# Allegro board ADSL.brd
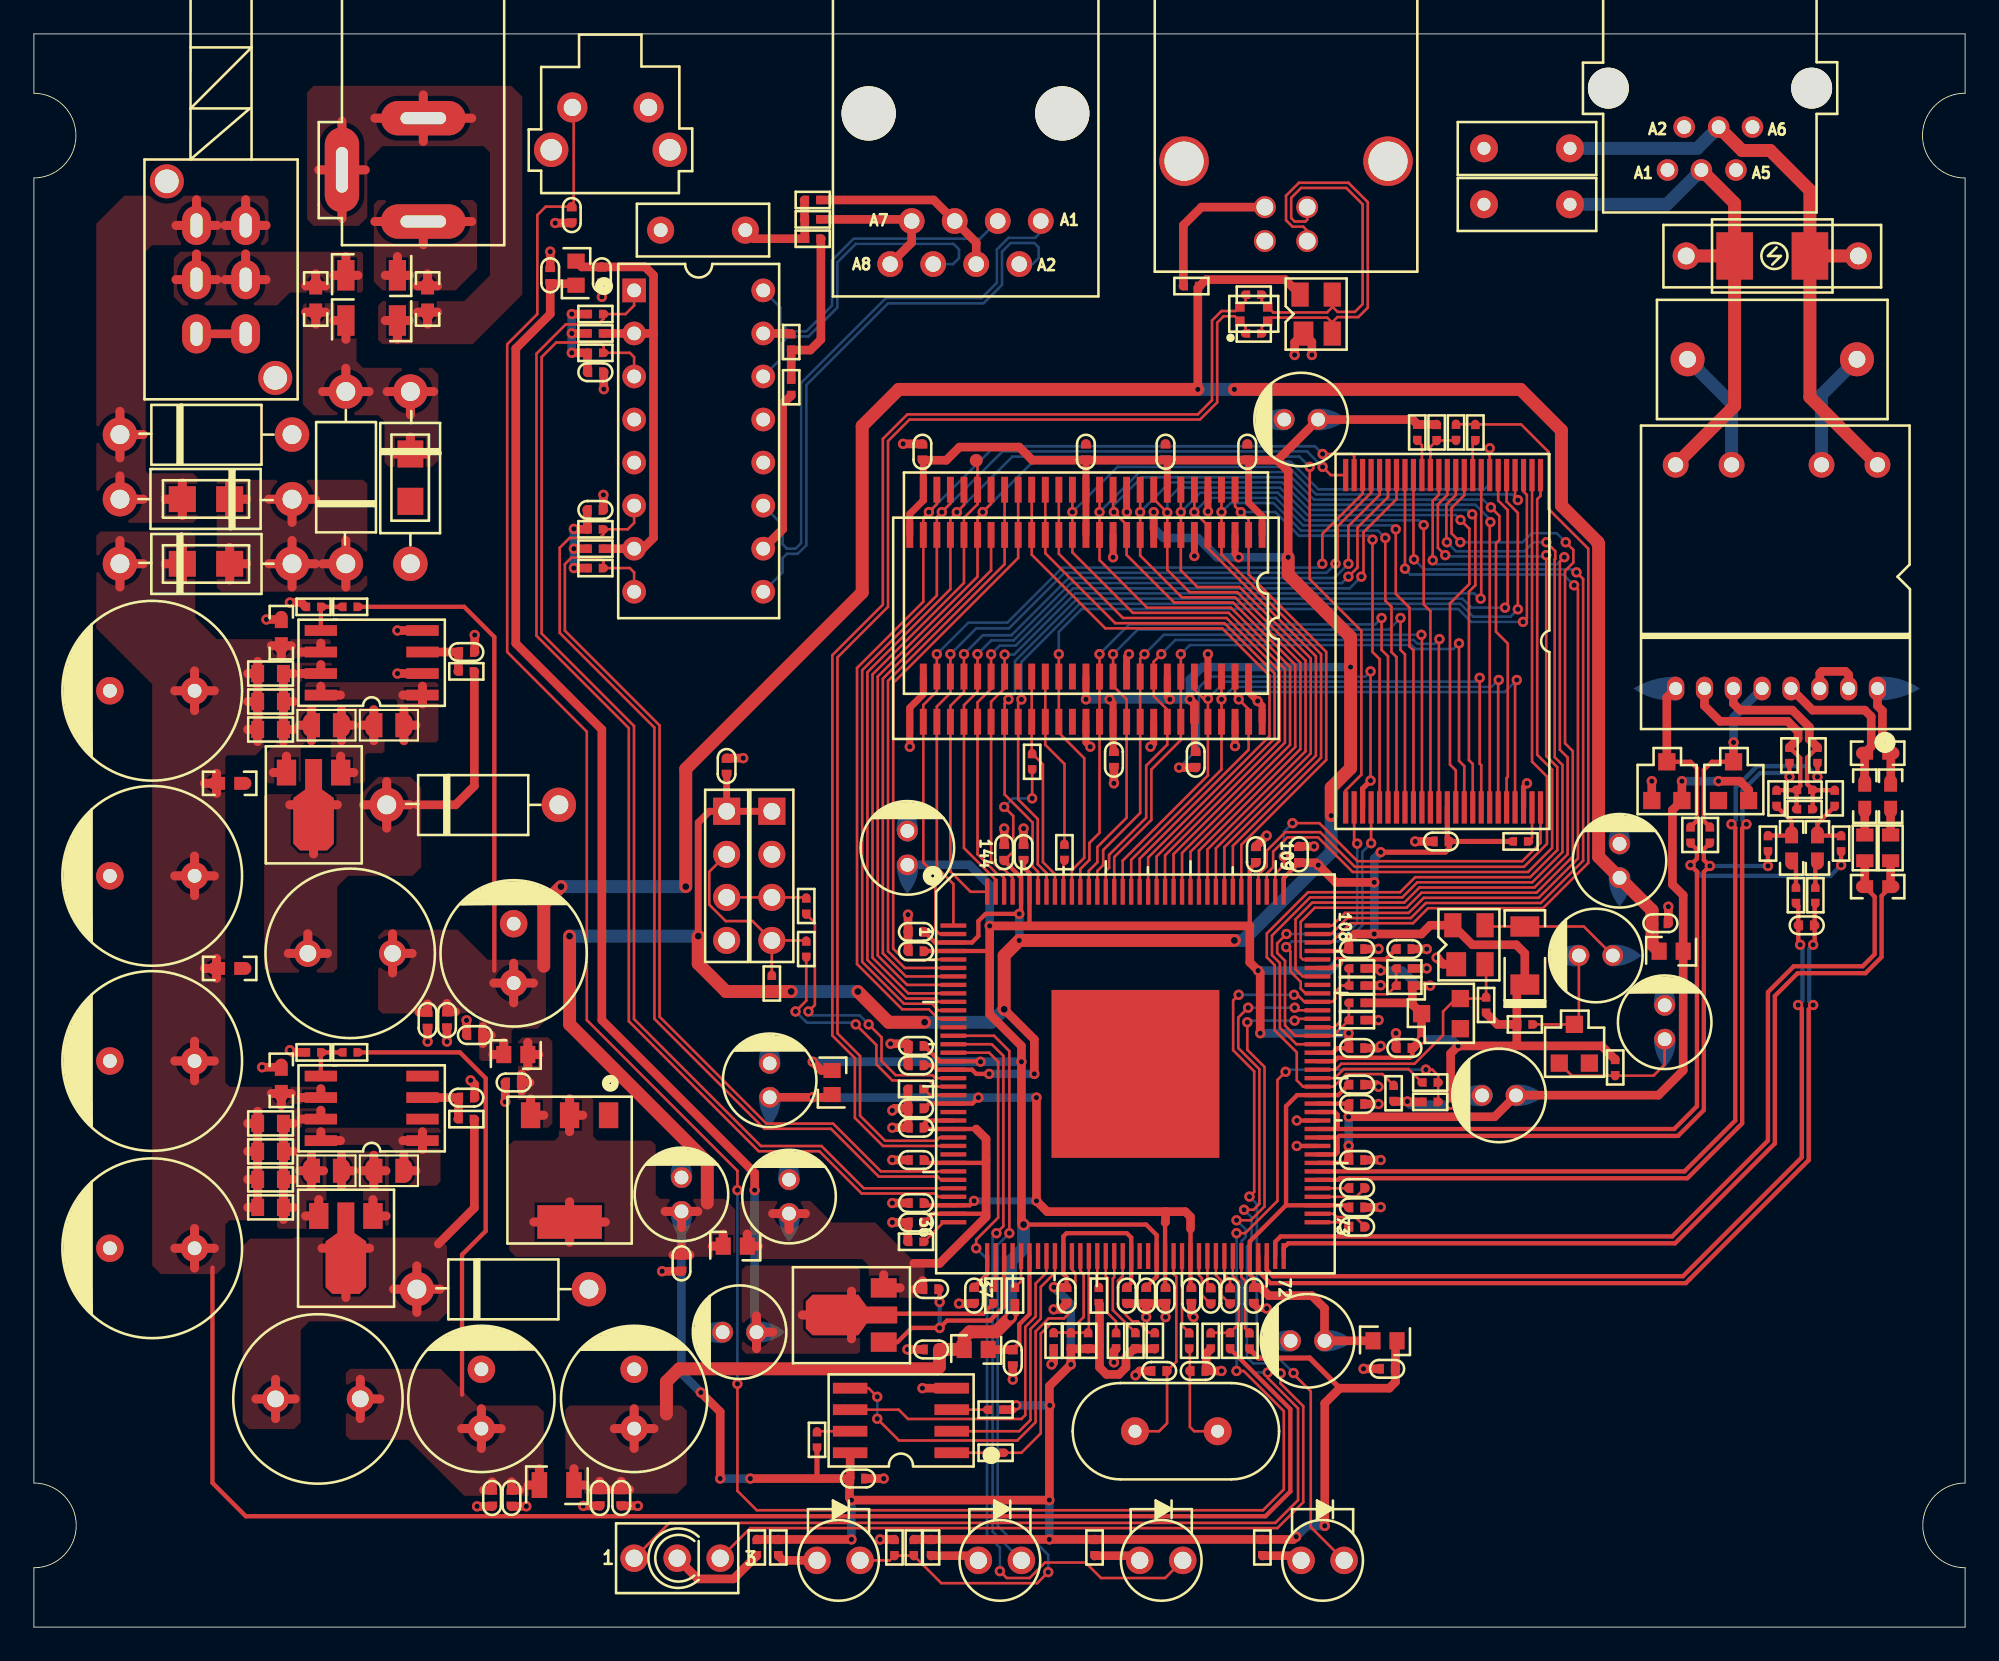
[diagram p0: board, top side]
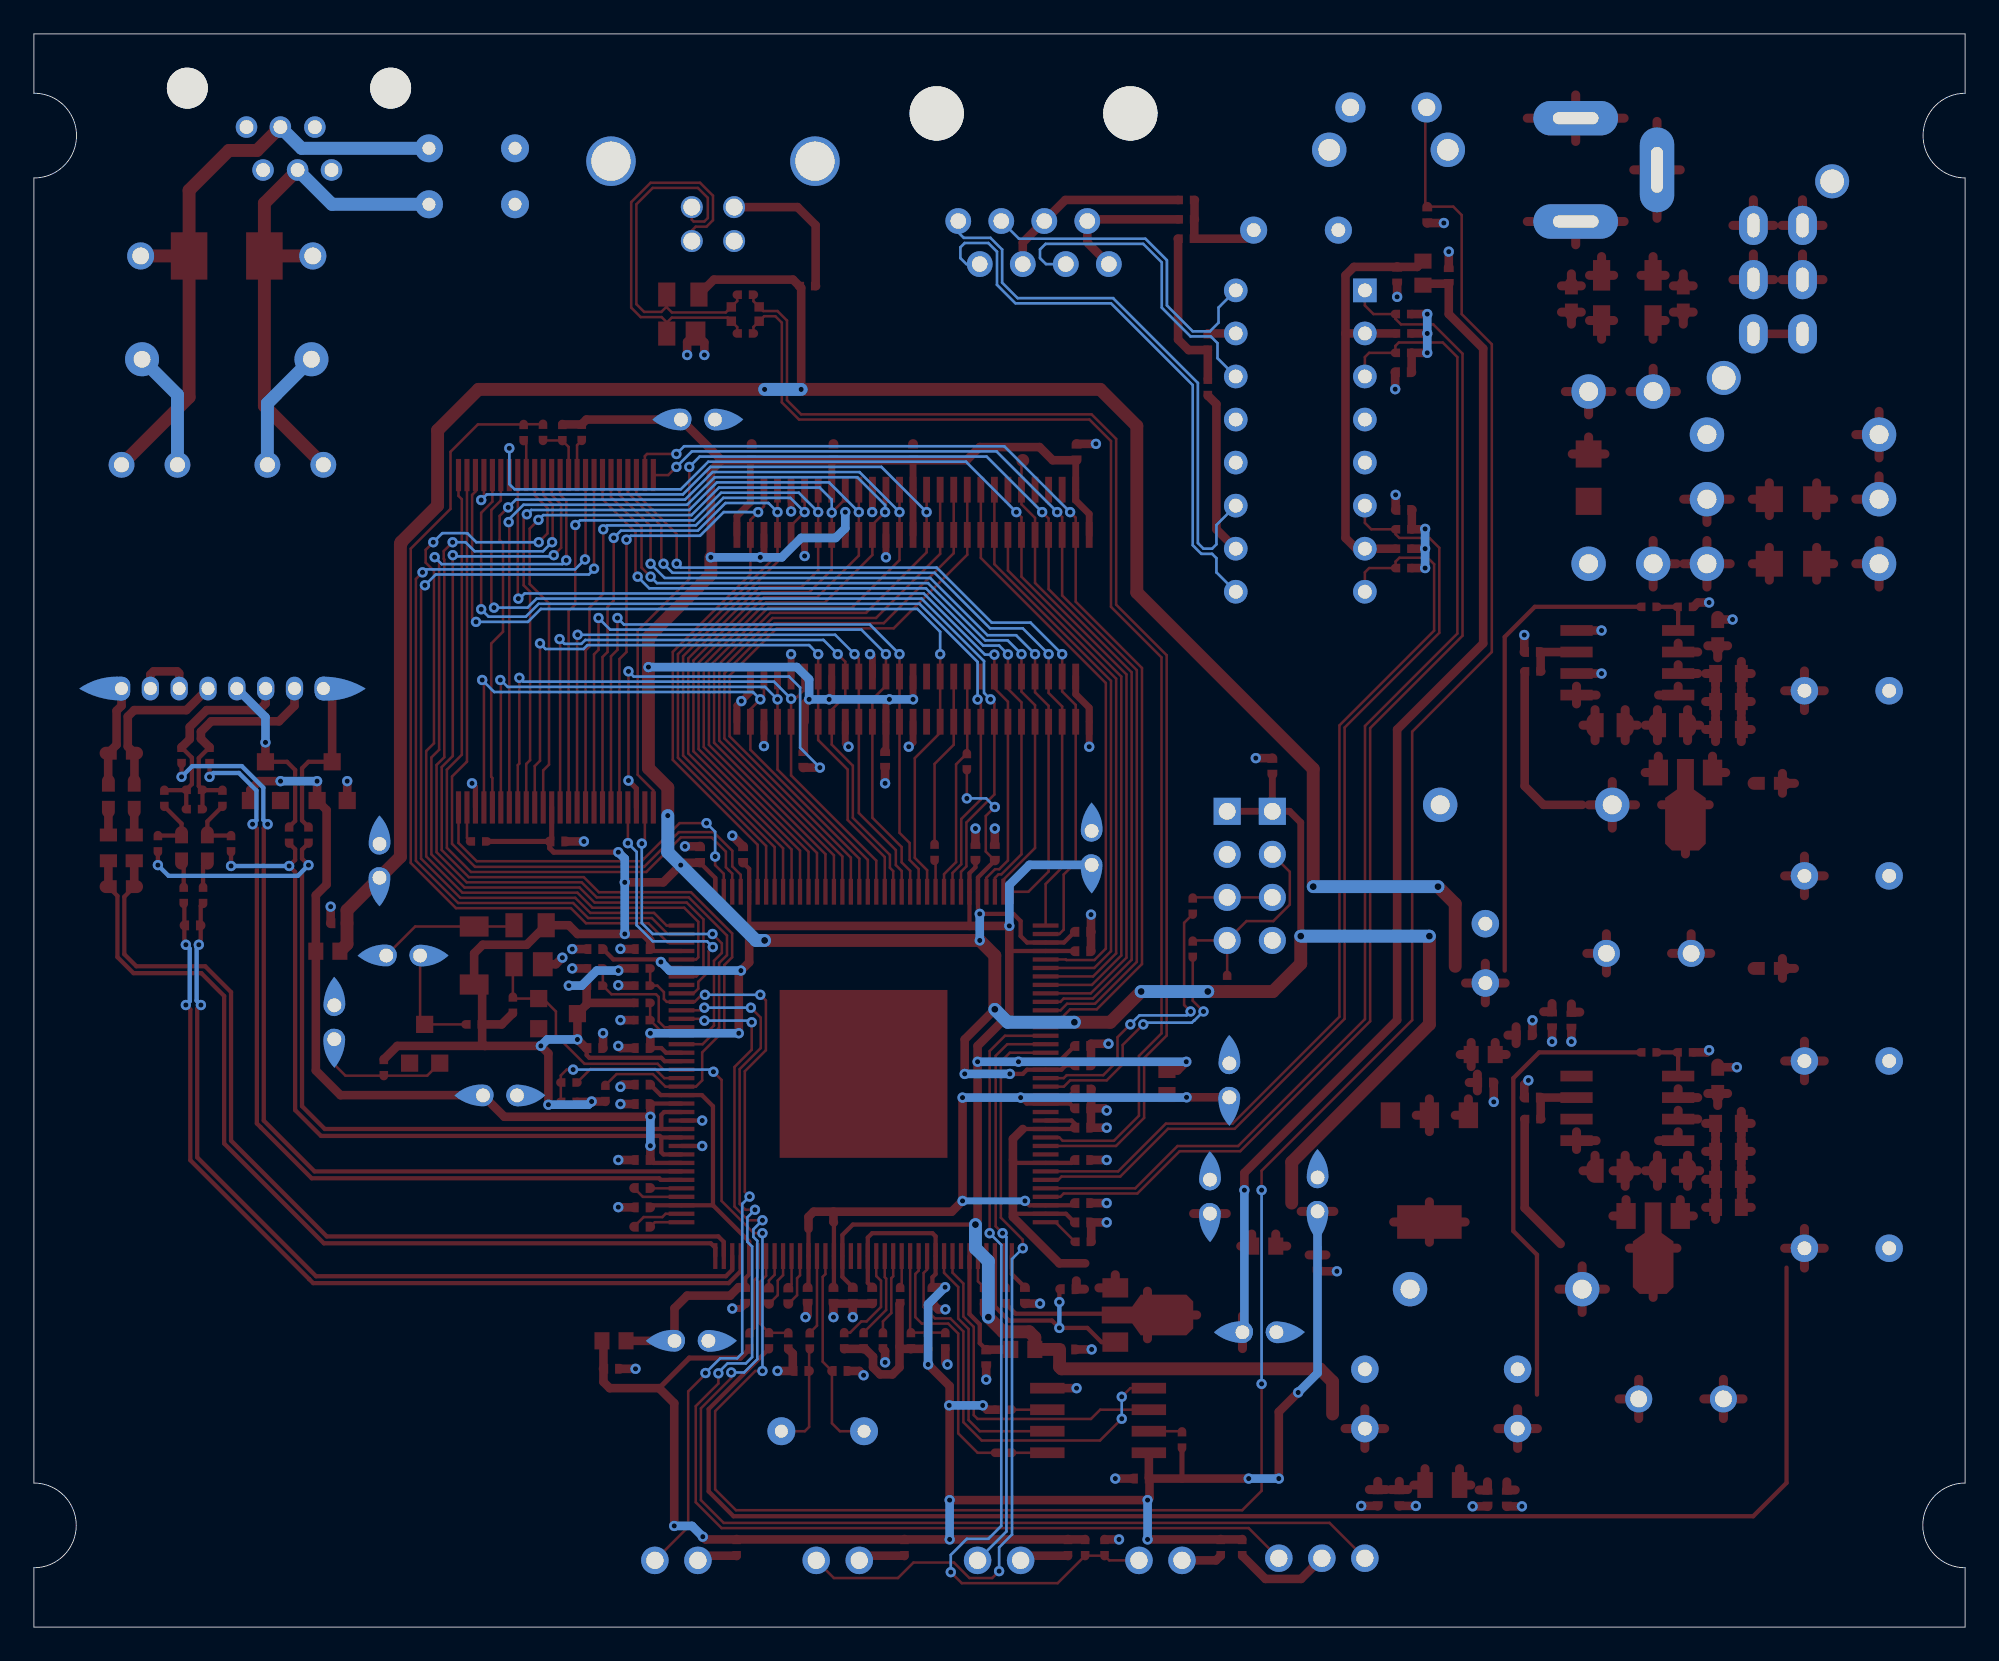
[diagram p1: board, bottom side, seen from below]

Outline 114 x 94 mm; copper layers: TOP, BOTTOM. Coordinates in mm from the lower left corner of the outline.
Outline path: 0,94 0,90.5 arc(2.5,88) 0,85.5 0,8.5 arc(2.5,6) 0,3.5 0,0 114,0 114,3.5 arc(111.5,6) 114,8.5 114,85.5 arc(111.5,88) 114,90.5 114,94 0,94

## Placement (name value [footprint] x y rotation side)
C318  C/104Z/25V/Y5V/C0603  [C0603]  23.24 78.36 0 top
C319  C/104Z/25V/Y5V/C0603  [C0603]  16.64 78.36 0 top
C320  C/103Z/25V/Y5V/C0603  [C0603]  14.61 32.26 180 top
C321  C/104Z/25V/Y5V/C0603  [C0603]  11.56 49.78 90 top
C322  C/391/J/50V/NPO/C0402  [C0402]  25.53 57.53 90 top
C323  C/104M/10V/X5R/C0402  [C0402]  26.04 34.92 270 top
C324  C/102K/50V/X7R/C0402  [C0402]  23.24 35.81 0 top
C325  C/103Z/25V/Y5V/C0603  [C0603]  14.61 58.67 180 top
C326  C/104Z/25V/Y5V/C0603  [C0603]  11.56 38.86 90 top
C327  C/391/J/50V/NPO/C0402  [C0402]  25.53 31.24 90 top
C328  C/104M/10V/X5R/C0402  [C0402]  27.05 7.62 0 top
C329  C/102K/50V/X7R/C0402  [C0402]  28.19 7.62 0 top
C331  C/104M/10V/X5R/C0402  [C0402]  28.32 32.13 270 top
C333  C/104M/10V/X5R/C0402  [C0402]  80.9 34.16 270 top
C334  C/561/J/50V/NPO/C0402  [C0402]  78.11 25.91 270 top
C335  C/181/J/50V/NPO/C0402  [C0402]  69.47 19.56 0 top
C336  C/181/J/50V/NPO/C0402  [C0402]  70.61 19.56 0 top
C337  C/104M/10V/X5R/C0402  [C0402]  78.11 23.62 270 top
C338  C/330/J/50V/NPO/C0402  [C0402]  68.71 15.11 90 top
C339  C/330/J/50V/NPO/C0402  [C0402]  66.42 15.11 270 top
C340  C/104M/10V/X5R/C0402  [C0402]  31.75 83.31 180 top
C341  C/104M/10V/X5R/C0402  [C0402]  83.06 46.35 90 top
C342  C/104M/10V/X5R/C0402  [C0402]  33.15 74.04 90 top
C343  C/104M/10V/X5R/C0402  [C0402]  33.15 65.91 270 top
C344  C/104M/10V/X5R/C0402  [C0402]  33.53 79.76 180 top
C345  C/33nF/630V/DIP  [C-13X6_4-10]  102.62 74.8 180 top
C346  C/221/J/50V/NPO/C0603  [C0603]  108.84 51.56 90 top
C347  C/101/J/50V/NPO/C0603  [C0603]  108.84 43.69 90 top
C348  C/152/J/50V/NPO/C0603  [C0603]  108.08 49.02 180 top
C349  C/152/J/50V/NPO/C0603  [C0603]  109.6 49.02 180 top
C350  C/5600PF/J/50V/NPO/C0603  [C0603]  105.28 45.97 0 top
C351  C/5600PF/J/50V/NPO/C0603  [C0603]  103.76 45.97 0 top
C352  NI/C/39pF/2kV/DIP  [C-7_62X2_54-5_08]  88.14 87.25 180 top
C353  NI/C/39pF/2kV/DIP  [C-7_62X2_54-5_08]  88.14 83.95 180 top
C354  C/102/M/2KV/DIP  [C-7_2X2_5-5]  39.5 82.42 180 top
C355  C/104M/10V/X5R/C0402  [C0402]  55.5 19.56 180 top
C358  C/104M/10V/X5R/C0402  [C0402]  58.42 45.72 0 top
C359  C/104M/10V/X5R/C0402  [C0402]  52.07 39.88 90 top
C360  C/104M/10V/X5R/C0402  [C0402]  52.96 16.38 90 top
C361  C/104M/10V/X5R/C0402  [C0402]  33.4 7.62 180 top
C362  C/104M/10V/X5R/C0402  [C0402]  34.67 7.62 180 top
C363  C/104M/10V/X5R/C0402  [C0402]  65.66 19.56 180 top
C364  C/104M/10V/X5R/C0402  [C0402]  78.11 34.16 270 top
C365  C/104M/10V/X5R/C0402  [C0402]  80.9 40.01 270 top
C366  C/104M/10V/X5R/C0402  [C0402]  72.14 45.59 0 top
C367  C/104M/10V/X5R/C0402  [C0402]  52.07 34.29 90 top
C368  C/104M/10V/X5R/C0402  [C0402]  57.78 15.88 180 top
C369  C/104M/10V/X5R/C0402  [C0402]  78.11 30.86 270 top
C370  C/104M/10V/X5R/C0402  [C0402]  96.01 41.53 270 top
C371  C/104M/10V/X5R/C0402  [C0402]  78.11 27.56 270 top
C372  C/104M/10V/X5R/C0402  [C0402]  52.07 27.56 90 top
C373  C/104M/10V/X5R/C0402  [C0402]  52.07 23.88 90 top
C374  C/104M/10V/X5R/C0402  [C0402]  52.07 29.46 90 top
C375  C/104M/10V/X5R/C0402  [C0402]  79.88 15.24 90 top
C376  C/104M/10V/X5R/C0402  [C0402]  38.23 21.46 180 top
C377  C/104M/10V/X5R/C0402  [C0402]  64.52 19.56 180 top
C378  C/104M/10V/X5R/C0402  [C0402]  57.28 45.72 0 top
C379  C/104M/10V/X5R/C0402  [C0402]  60.96 19.56 180 top
C380  C/104M/10V/X5R/C0402  [C0402]  52.07 33.15 90 top
C381  C/104M/10V/X5R/C0402  [C0402]  52.07 41.02 90 top
C382  C/104M/10V/X5R/C0402  [C0402]  72.01 19.56 180 top
C383  C/104M/10V/X5R/C0402  [C0402]  78.11 32 270 top
C384  C/104M/10V/X5R/C0402  [C0402]  78.11 24.77 270 top
C385  C/104M/10V/X5R/C0402  [C0402]  52.07 30.61 90 top
C386  C/104M/10V/X5R/C0402  [C0402]  68.33 19.56 180 top
C387  C/104M/10V/X5R/C0402  [C0402]  52.07 25.02 90 top
C388  C/104M/10V/X5R/C0402  [C0402]  66.8 19.56 180 top
C389  C/104M/10V/X5R/C0402  [C0402]  52.96 19.94 270 top
C391  C/104M/10V/X5R/C0402  [C0402]  30.48 79.76 0 top
C392  C/104M/10V/X5R/C0402  [C0402]  74.68 45.59 0 top
C393  C/104M/10V/X5R/C0402  [C0402]  78.11 40.01 270 top
C394  C/104M/10V/X5R/C0402  [C0402]  40.89 50.8 0 top
C395  C/104M/10V/X5R/C0402  [C0402]  63.75 51.18 180 top
C396  C/104M/10V/X5R/C0402  [C0402]  52.45 69.34 0 top
C397  C/104M/10V/X5R/C0402  [C0402]  68.58 51.18 180 top
C398  C/104M/10V/X5R/C0402  [C0402]  71.63 69.34 0 top
C399  C/104M/10V/X5R/C0402  [C0402]  66.8 69.34 0 top
C400  C/104M/10V/X5R/C0402  [C0402]  62.1 69.34 0 top
C404  C/104M/10V/X5R/C0402  [C0402]  24.38 35.81 180 top
C405  NI/C/104M/10V/X5R/C0402  [C0402]  48.64 8.76 270 top
C832  NI/C_0402  [C0402]  104.65 41.4 270 top
CAP1  C/470UF/M/25V/10*16/105C  [C-D10XH16-5]  6.99 44.32 270 top
CAP2  NI/C/470UF/M/25V/10*16/105C  [C-D10XH16-5]  6.99 55.24 270 top
CAP3  C/1000uF/M/6.3V/8*12  [C-D8XH12-3_5]  28.32 39.75 180 top
CAP4  C/470UF/M/25V/10*16/105C  [C-D10XH16-5]  6.99 33.4 270 top
CAP5  NI/C/470UF/M/25V/10*16/105C  [C-D10XH16-5]  6.99 22.35 270 top
CAP6  C/1000uF/M/6.3V/8*12  [C-D8XH12-3_5]  26.42 13.46 180 top
CAP8  C/470uF/M/6.3V/8*11  [C-D8XH12-3_5]  35.43 13.46 180 top
CAP12  C/47uF/M/25V/5*11/105C  [C-D5XH11-2]  51.56 45.97 180 top
CAP13  C/47uF/M/25V/5*11/105C  [C-D5XH11-2]  86.49 31.37 270 top
CAP14  C/47uF/M/25V/5*11/105C  [C-D5XH11-2]  44.58 25.4 180 top
CAP16  C/47uF/M/25V/5*11/105C  [C-D5XH11-2]  75.18 16.89 270 top
CAP17  C/47uF/M/25V/5*11/105C  [C-D5XH11-2]  43.43 32.26 180 top
CAP18  C/47uF/M/25V/5*11/105C  [C-D5XH11-2]  93.6 45.21 180 top
CAP19  C/47uF/M/25V/5*11/105C  [C-D5XH11-2]  41.66 17.4 270 top
CAP20  C/47uF/M/25V/5*11/105C  [C-D5XH11-2]  74.8 71.25 270 top
CAP21  C/47uF/M/25V/5*11/105C  [C-D5XH11-2]  38.23 25.53 180 top
CAP22  NI/C/47uF/M/25V/5*11/105C  [C-D5XH11-2]  96.27 35.69 180 top
CAP23  NI/C/22uF/M/25V/5*11/105C  [C-D5XH11-2]  92.2 39.62 270 top
D12  D/1N4004/400V1A/DIP  [D-DO41-10_16]  18.41 67.82 270 top
D13  D/1N4004/400V1A/DIP  [D-DO41-10_16]  10.16 66.55 0 top
D14  D/1N4004/400V1A/DIP  [D-DO41-10_16]  22.23 67.82 90 top
D15  D/1N4004/400V1A/DIP  [D-DO41-10_16]  10.16 70.36 180 top
D16  D/1N5819/40V1A  [D-DO41-10_16]  25.91 48.51 180 top
D17  D/1N5819/40V1A  [D-DO41-10_16]  27.69 19.94 180 top
D18  BAV99 SOT23-3  [SOT-23-3P]  96.39 49.91 0 top
D19  BAV99 SOT23-3  [SOT-23-3P]  100.33 49.91 0 top
D20  D_ARRAY-SR05  [SOT-143-4P]  75.69 77.47 270 top
D22  NI/LL4148  [D-3_85X1_7]  88.01 39.62 0 top
D23  NI/D/1N5819/40V1A  [D-DO41-10_16]  10.16 62.74 180 top
FB7  FB600ohm@100MHz +-25% 1500mA SMD1206  [L1206]  19.94 79.76 270 top
FB8  FB600ohm@100MHz +-25% 1500mA SMD1206  [L1206]  19.94 77.09 270 top
FB10  FB/2A/220ohm/100MHZ/0.05ohm/0805  [L0805]  30.86 8.38 90 top
FB13  FB/0.5A/600ohm/100MHZ/0.4ohm/0603  [L0603]  32 79.88 0 top
FB14  FB/0.5A/600ohm/100MHZ/0.4ohm/0603  [L0603]  55.63 16.38 90 top
FB15  FB/0.5A/600ohm/100MHZ/0.4ohm/0603  [L0603]  41.4 22.48 90 top
FB17  FB/0.5A/600ohm/100MHZ/0.4ohm/0603  [L0603]  79.76 16.89 270 top
FB18  FB/0.5A/600ohm/100MHZ/0.4ohm/0603  [L0603]  47.12 32.13 0 top
FB20  FB/0.5A/600ohm/100MHZ/0.4ohm/0603  [L0603]  96.65 39.88 90 top
FB21  FB/0.5A/600ohm/100MHZ/0.4ohm/0603  [L0603]  28.45 33.78 90 top
J5  AC_IN  [JACK-14_9X9-3P]  22.99 85.98 90 top
J6  HEADER_CN_4P-2_54  [CN-4P-2_54]  43.56 44.32 270 top
J8  USB_16_5X12-4P  [USB-16_5X12-4P]  73.91 88.52 180 top
J9  RJ45  [RJ45-18X15-8PS1]  54.99 88.14 0 top
J10  RJ11  [RJ11-13X12-6P]  98.93 90.81 0 top
J11  HEADER_CN_4P-2_54  [CN-4P-2_54]  40.89 44.32 270 top
L1  L/220uH/1A  [L-D9_5-5]  18.67 39.75 0 top
L2  L/220uH/1A  [L-D9_5-5]  16.76 13.46 0 top
LED1  LED_6_6X3_5-3P  [LED-6_6X3_5-3P]  37.97 4.06 0 top
LED2  LED_D4_2-2_54  [LED-D4_2-2_54]  47.5 3.94 0 top
LED3  LED_D4_2-2_54  [LED-D4_2-2_54]  57.02 3.94 0 top
LED4  LED_D4_2-2_54  [LED-D4_2-2_54]  66.55 3.94 0 top
LED5  LED_D4_2-2_54  [LED-D4_2-2_54]  76.07 3.94 0 top
Q304  NI/NPN_3P-1  [SOT-23-3P]  90.93 34.42 0 top
Q305  2SB1188/32V/2A/SOT89  [SOT-89-3P]  16.51 50.42 180 top
Q306  2SB1188/32V/2A/SOT89  [SOT-89-3P]  18.41 24.26 180 top
Q307  2SB1188/32V/2A/SOT89  [SOT-89-3P]  50.16 18.41 90 top
R329  R/1/R0603/5%  [R0603]  13.97 56.26 270 top
R330  R/1/R0603/5%  [R0603]  13.97 54.61 270 top
R331  R/1/R0603/5%  [R0603]  13.97 52.96 270 top
R332  R/470/R0805/5%  [R0805]  17.27 53.21 90 top
R333  R/220/R0805/5%  [R0805]  20.95 53.21 270 top
R336  R/390K/R0402/5%  [R0402]  25.53 56.39 270 top
R337  R/3.01K/R0402/1%  [R0402]  18.67 60.2 270 top
R338  R/1k/R0402/1%  [R0402]  16.51 60.2 90 top
R339  R/1/R0603/5%  [R0603]  13.97 29.72 270 top
R340  R/1/R0603/5%  [R0603]  13.97 28.07 270 top
R341  R/1/R0603/5%  [R0603]  13.97 26.42 270 top
R342  R/1/R0603/5%  [R0603]  13.97 24.77 270 top
R343  R/470/R0805/5%  [R0805]  17.27 26.92 90 top
R344  R/220/R0805/5%  [R0805]  20.95 26.92 270 top
R347  R/390K/R0402/5%  [R0402]  25.53 29.97 270 top
R348  R/1k/R0402/1%  [R0402]  18.67 33.91 270 top
R349  R/4.99K/R0402/1%  [R0402]  16.51 33.91 90 top
R356  R/1k/R0402/5%  [R0402]  82.42 32.13 270 top
R357  R/0/R0402/5%  [R0402]  68.2 16.89 0 top
R358  R/330/R0402/1%  [R0402]  42.67 4.7 0 top
R359  R/330/R0402/1%  [R0402]  43.94 4.7 0 top
R360  R/330/R0402/1%  [R0402]  52.96 4.7 0 top
R361  R/330/R0402/1%  [R0402]  62.61 4.7 0 top
R362  R/330/R0402/1%  [R0402]  72.52 4.7 0 top
R364  R/1k/R0402/5%  [R0402]  63.88 16.89 180 top
R365  NI/R/10K/R0402/1%  [R0402]  61.21 16.89 180 top
R366  R/4.7K/R0402/1%  [R0402]  60.2 16.89 180 top
R367  NI/R/10K/R0402/1%  [R0402]  51.94 4.7 0 top
R368  R/120/R0402/1%  [R0402]  50.8 4.7 0 top
R369  R/4.7K/R0402/1%  [R0402]  71.75 16.89 0 top
R370  R/10K/R0402/1%  [R0402]  78.11 38.86 270 top
R371  NI/R/10K/R0402/1%  [R0402]  78.11 37.85 270 top
R372  NI/R/10K/R0402/1%  [R0402]  78.11 36.83 270 top
R373  R/10K/R0402/1%  [R0402]  78.11 35.81 270 top
R374  R/1k/R0402/5%  [R0402]  45.59 42.55 0 top
R375  NI/R/100k/R0402/5%  [R0402]  88.01 35.56 90 top
R376  NI/R/100k/R0402/5%  [R0402]  93.34 33.02 0 top
R377  R/270/R0603/1%  [R0603]  108.08 45.97 180 top
R378  R/270/R0603/1%  [R0603]  109.6 45.97 180 top
R379  R/1k/R0402/5%  [R0402]  66.17 16.89 180 top
R380  R/1k/R0402/5%  [R0402]  62.87 19.56 180 top
R381  R/0/R0402/5%  [R0402]  104.52 49.4 90 top
R382  R/0/R0402/5%  [R0402]  104.52 48.26 90 top
R383  R/0/R0402/5%  [R0402]  102.36 46.23 0 top
R384  NI/R/0/R0402/5%  [R0402]  102.87 48.9 180 top
R385  NI/R/0/R0402/5%  [R0402]  106.3 48.9 180 top
R386  R/0/R0402/5%  [R0402]  106.68 46.23 0 top
R387  NI/R/1k/R0402/5%  [R0402]  62.23 16.89 180 top
R388  R/1k/R0402/5%  [R0402]  65.02 16.89 180 top
R389  NI/R/10K/R0402/1%  [R0402]  80.9 37.85 270 top
R390  R/10K/R0402/1%  [R0402]  80.9 38.86 270 top
R391  R/4.7K/R0402/1%  [R0402]  58.93 51.05 180 top
R392  R/8.87K/R0402/1%  [R0402]  52.07 31.75 270 top
R393  NI/R/0/R0402/5%  [R0402]  68.33 79.12 90 top
R397  R/1k/R0402/5%  [R0402]  45.59 40.01 0 top
R398  R/75/R0402/5%  [R0402]  44.7 75.82 180 top
R399  R/75/R0402/5%  [R0402]  44.7 73.15 0 top
R400  R/75/R0402/5%  [R0402]  45.97 83.06 270 top
R401  R/75/R0402/5%  [R0402]  45.97 84.2 270 top
R402  R/0/R0402/5%  [R0402]  45.97 81.92 90 top
R403  R/49.9/R0402/1%  [R0402]  33.15 77.47 90 top
R404  R/49.9/R0402/1%  [R0402]  33.15 75.18 90 top
R405  R/49.9/R0402/1%  [R0402]  33.15 64.77 270 top
R406  R/49.9/R0402/1%  [R0402]  33.15 62.48 270 top
R407  NI/R/0/R0402/5%  [R0402]  33.15 76.33 270 top
R408  NI/R/0/R0402/5%  [R0402]  33.15 63.63 270 top
R409  R/11.5K/R0402/1%  [R0402]  52.07 22.73 270 top
R411  R/0/R0402/5%  [R0402]  56.64 19.56 180 top
R412  R/4.7K/R0402/1%  [R0402]  82.42 30.99 270 top
R413  R/4.7K/R0402/1%  [R0402]  85.72 36.7 0 top
R414  R/4.7K/R0402/1%  [R0402]  80.26 31.5 0 top
R415  R/0/R0402/5%  [R0402]  85.09 70.48 0 top
R416  NI/R/0/R0402/5%  [R0402]  83.95 70.48 180 top
R417  R/1k/R0402/5%  [R0402]  82.8 70.48 0 top
R418  R/10K/R0402/1%  [R0402]  87.76 46.35 270 top
R419  R/10K/R0402/1%  [R0402]  81.66 70.48 180 top
R420  NI/R/10K/R0402/1%  [R0402]  46.23 11.05 0 top
R421  NI/R/10K/R0402/1%  [R0402]  56.77 12.83 90 top
R422  NI/R/0/R0402/5%  [R0402]  56.77 10.29 270 top
R423  R/931/R0402/5%  [R0402]  69.47 16.89 0 top
R424  R/3.57k/R0402/5%  [R0402]  70.61 16.89 180 top
R425  R/2.4/R0402/5%  [R0402]  97.79 46.74 0 top
R426  R/2.4/R0402/5%  [R0402]  98.93 46.74 0 top
R427  NI/R/43/R0402/1%  [R0402]  105.28 51.44 0 top
R428  NI/R/43/R0402/1%  [R0402]  103.63 51.44 0 top
R429  R/160/R0402/1%  [R0402]  104.01 43.18 0 top
R430  R/160/R0402/1%  [R0402]  105.16 43.18 0 top
R431  R/75/R0402/5%  [R0402]  60.83 45.72 0 top
R432  NI/R/0/R0402/5%  [R0402]  57.91 19.56 180 top
R433  R/0/R0402/5%  [R0402]  72.01 78.61 270 top
R434  R/0/R0402/5%  [R0402]  72.01 76.33 270 top
R435  R/10K/R0402/1%  [R0402]  43.56 37.97 180 top
R436  R/0/R1206/5%  [R1206]  10.16 62.74 270 top
R437  NI/R/0/R1206/5%  [R1206]  10.16 66.55 90 top
R438  NI/R/0/R1206/5%  [R1206]  22.23 67.82 180 top
RV1  NC/SPG301K  [DT-12_2X3-10]  102.62 80.9 180 top
RV2  P310SA  [DT-214AA]  102.62 80.9 270 top
S1  SW PUSHBUTTON  [SW-7_8X6_8-4P]  34.04 89.66 180 top
SW1  SW,PWR_Push,SPST,0.5A@50VDC  [SW-12_4X7_8-8P]  11.05 79.5 90 top
T4  T_H1102-16P  [DIP-16]  39.24 69.98 180 top
T5  T-LAL0683-ALT-12P  [T-17X15-12P]  102.87 61.98 90 top
T6  NI/DLW21HN900SQ2  [L-2X1_2-4P]  72.01 77.47 0 top
TP1  T_POINT_R  [TP_30]  55.63 68.83 0 top
U1  AMAZON-SE  [QFP-22X22-145P-0_5]  65.02 32.64 270 top
U11  MC34063A  [SO-6_6X4-8P-1_27]  19.94 56.9 0 top
U12  MC34063A  [SO-6_6X4-8P-1_27]  19.94 30.61 0 top
U14  AMS1117  [SOT-223-4P]  31.62 27.05 90 top
U15  MAX809STRG  [SOT-23-3P]  83.06 36.2 90 top
U26  NI/FLASH_SO8  [SO-6X5-8P-1_27]  51.18 12.19 0 top
U27  K4S641632K-UC60  [SO-11_8X22-54P-0_8]  62.1 58.93 90 top
U28  NI/K46S161622H-TC80  [SO-11_8X21-50P-0_8]  62.1 61.59 90 top
U29  MX29LV640  [SO-20X12-48P-0_5S1]  83.19 58.17 90 top
U30  NI/MAX811 SEUS-T  [SOT-143-4P]  84.71 40.26 270 top
Y3  Y/36MHz/18PF/20PPM  [OSC-11_5X5-2P]  67.44 11.56 0 top

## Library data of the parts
C318-C321 C325 C326 C346-C351 = C_0603
C322-C324 C327-C329 C331 C333-C344 C355 C358-C389 C391-C400 C404 C405 C832 = C_0402
C345 C352-C354 = CAP
CAP1-CAP6 CAP8 CAP12-CAP14 CAP16-CAP23 = CAP_X
D12-D17 D22 D23 = Diode
D18 D19 = D_DUAL-AC
D20 = D_ARRAY-SR05
FB7 FB8 FB10 FB13-FB15 FB17 FB18 FB20 FB21 = FB
J5 = JACK_14_9X9-3P
J6 J11 = CN_4P-2_1
J8 = USB_16_4
J9 = RJ45_18X15-8PS1
J10 = RJ11_13X12-6P
L1 L2 = Inductor
LED1 = LED_6_6X3_5-3P
LED2-LED5 = LED_D4_2-2_54
Q304 = NPN_3P-1
Q305-Q307 = PNP_3P-2
R329-R331 R339-R342 R377 R378 = R_0603
R332 R333 R343 R344 R436-R438 = R_1206
R336-R338 R347-R349 R356-R362 R364-R376 R379-R393 R397-R409 R411-R435 = R_0402
RV1 RV2 = DT_GDT
S1 = SW PUSHBUTTON_1
SW1 = SW_12_4X7_9
T4 = T_H1102-16P
T5 = T-LAL0683-ALT-12P
T6 = PE-65855
TP1 = TP_30
U1 = Amazon-SE-PSB50601
U11 U12 = MC34063A
U14 = LM1117_2
U15 = MAX809STRG_0
U26 = FLASH_SO8
U27 = HYB39S512160AT_0
U28 = K46S161622H-TC80
U29 = MX29LV320_0
U30 = XC61B/TOREX_1
Y3 = XTAL_2P

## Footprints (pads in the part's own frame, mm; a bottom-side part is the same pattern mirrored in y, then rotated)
C0402
  custom 0.14x0.14 smd: 1(0,0.47) 2(0,-0.495)
C0603
  custom 0.191x0.191 smd: 1(0,0.775) 2(0,-0.775)
C-7_2X2_5-5
  round 1.6 hole 0.813: 1(-2.499,0) 2(2.499,0)
C-7_62X2_54-5_08
  round 1.651 hole 0.762: 1(-2.54,0) 2(2.54,0)
C-13X6_4-10
  round 2.007 hole 0.991: 1(-5,0) 2(5,0)
C-D5XH11-2
  round 1.219 hole 0.813: 1(0,1.001) 2(0,-1.001)
C-D8XH12-3_5
  round 1.626 hole 0.813: 1(0,1.75) 2(0,-1.75)
C-D10XH16-5
  round 1.626 hole 0.813: 1(0,2.499) 2(0,-2.499)
CN-4P-2_54
  rect 1.6x1.6 hole 0.991: 1(-3.81,0)
  round 1.6 hole 0.991: 2(-1.27,0) 3(1.27,0) 4(3.81,0)
D-3_85X1_7
  rect 1.702x1.194 smd: 1(0,1.712) 2(0,-1.712)
D-DO41-10_16
  round 2.032 hole 1.118: 1(-5.08,0) 2(5.08,0)
DIP-16
  rect 1.397x1.397 hole 0.813: 1(3.81,-8.89)
  round 1.397 hole 0.813: 2(3.81,-6.35) 3(3.81,-3.81) 4(3.81,-1.27) 5(3.81,1.27) 6(3.81,3.81) 7(3.81,6.35) 8(3.81,8.89) 9(-3.81,8.89) 10(-3.81,6.35) 11(-3.81,3.81) 12(-3.81,1.27) 13(-3.81,-1.27) 14(-3.81,-3.81) 15(-3.81,-6.35) 16(-3.81,-8.89)
DT-12_2X3-10
  round 1.6 hole 0.991: 1(-5.08,0) 2(5.08,0)
DT-214AA
  rect 2.794x2.159 smd: 1(0,2.223) 2(0,-2.223)
JACK-14_9X9-3P
  oval 2.032x5.004 hole 0.711x2.692: 1(-3.048,0) 2(3.048,0)
  oval 5.004x2.032 hole 2.692x0.711: 3(0,4.8)
L0603
  rect 1.016x0.889 smd: 1(0,0.71) 2(0,-0.71)
L0805
  rect 1.524x0.914 smd: 1(0,1.02) 2(0,-1.02)
L1206
  rect 1.803x1.016 smd: 1(0,1.52) 2(0,-1.52)
L-2X1_2-4P
  rect 0.559x0.559 smd: 1(-0.822,-0.422) 2(0.822,-0.422) 3(0.822,0.422) 4(-0.822,0.422)
L-D9_5-5
  round 1.6 hole 0.991: 1(-2.497,0) 2(2.504,0)
LED-6_6X3_5-3P
  round 1.626 hole 1.016: 1(-2.54,0) 2(0,0) 3(2.54,0)
LED-D4_2-2_54
  round 1.626 hole 1.016: 1(-1.27,0) 2(1.27,0)
OSC-11_5X5-2P
  round 1.651 hole 0.762: 1(-2.44,0) 2(2.44,0)
QFP-22X22-145P-0_5
  rect 0.254x1.524 smd: 1(-8.752,-10.747) 2(-8.252,-10.747) 3(-7.752,-10.747) 4(-7.252,-10.747) 5(-6.752,-10.747) 6(-6.252,-10.747) 7(-5.752,-10.747) 8(-5.251,-10.747) 9(-4.751,-10.747) 10(-4.251,-10.747) 11(-3.751,-10.747) 12(-3.251,-10.747) 13(-2.751,-10.747) 14(-2.251,-10.747) 15(-1.751,-10.747) 16(-1.25,-10.747) 17(-0.75,-10.747) 18(-0.25,-10.747) 19(0.25,-10.747) 20(0.75,-10.747) 21(1.25,-10.747) 22(1.75,-10.747) 23(2.25,-10.747) 24(2.751,-10.747) 25(3.251,-10.747) 26(3.751,-10.747) 27(4.251,-10.747) 28(4.751,-10.747) 29(5.251,-10.747) 30(5.751,-10.747) 31(6.251,-10.747) 32(6.752,-10.747) 33(7.252,-10.747) 34(7.752,-10.747) 35(8.252,-10.747) 36(8.752,-10.747) 73(8.752,10.747) 74(8.252,10.747) 75(7.752,10.747) 76(7.252,10.747) 77(6.752,10.747) 78(6.252,10.747) 79(5.752,10.747) 80(5.251,10.747) 81(4.751,10.747) 82(4.251,10.747) 83(3.751,10.747) 84(3.251,10.747) 85(2.751,10.747) 86(2.251,10.747) 87(1.751,10.747) 88(1.25,10.747) 89(0.75,10.747) 90(0.25,10.747) 91(-0.25,10.747) 92(-0.75,10.747) 93(-1.25,10.747) 94(-1.75,10.747) 95(-2.25,10.747) 96(-2.751,10.747) 97(-3.251,10.747) 98(-3.751,10.747) 99(-4.251,10.747) 100(-4.751,10.747) 101(-5.251,10.747) 102(-5.751,10.747) 103(-6.251,10.747) 104(-6.752,10.747) 105(-7.252,10.747) 106(-7.752,10.747) 107(-8.252,10.747) 108(-8.752,10.747)
  rect 1.524x0.254 smd: 37(10.747,-8.752) 38(10.747,-8.252) 39(10.747,-7.752) 40(10.747,-7.252) 41(10.747,-6.752) 42(10.747,-6.252) 43(10.747,-5.752) 44(10.747,-5.251) 45(10.747,-4.751) 46(10.747,-4.251) 47(10.747,-3.751) 48(10.747,-3.251) 49(10.747,-2.751) 50(10.747,-2.251) 51(10.747,-1.751) 52(10.747,-1.25) 53(10.747,-0.75) 54(10.747,-0.25) 55(10.747,0.25) 56(10.747,0.75) 57(10.747,1.25) 58(10.747,1.75) 59(10.747,2.25) 60(10.747,2.751) 61(10.747,3.251) 62(10.747,3.751) 63(10.747,4.251) 64(10.747,4.751) 65(10.747,5.251) 66(10.747,5.751) 67(10.747,6.251) 68(10.747,6.752) 69(10.747,7.252) 70(10.747,7.752) 71(10.747,8.252) 72(10.747,8.752) 109(-10.747,8.752) 110(-10.747,8.252) 111(-10.747,7.752) 112(-10.747,7.252) 113(-10.747,6.752) 114(-10.747,6.252) 115(-10.747,5.752) 116(-10.747,5.251) 117(-10.747,4.751) 118(-10.747,4.251) 119(-10.747,3.751) 120(-10.747,3.251) 121(-10.747,2.751) 122(-10.747,2.251) 123(-10.747,1.751) 124(-10.747,1.25) 125(-10.747,0.75) 126(-10.747,0.25) 127(-10.747,-0.25) 128(-10.747,-0.75) 129(-10.747,-1.25) 130(-10.747,-1.75) 131(-10.747,-2.25) 132(-10.747,-2.751) 133(-10.747,-3.251) 134(-10.747,-3.751) 135(-10.747,-4.251) 136(-10.747,-4.751) 137(-10.747,-5.251) 138(-10.747,-5.751) 139(-10.747,-6.251) 140(-10.747,-6.752) 141(-10.747,-7.252) 142(-10.747,-7.752) 143(-10.747,-8.252) 144(-10.747,-8.752)
  rect 9.906x9.906 smd: 145(0,0)
R0402
  custom 0.127x0.127 smd: 1(0,0.473) 2(0,-0.485)
R0603
  rect 1.016x0.762 smd: 1(0,0.76) 2(0,-0.76)
R0805
  custom 0.254x0.254 smd: 1(0,0.889) 2(0,-0.889)
R1206
  rect 1.524x1.6 smd: 1(0,1.397) 2(0,-1.397)
RJ11-13X12-6P
  round 2.413 hole 2.413 unplated: (-5.992,-0.005) (6.008,-0.005)
  round 1.27 hole 0.813: A1(-2.501,-4.834) A2(-1.519,-2.304) A3(-0.501,-4.834) A4(0.517,-2.303) A5(1.539,-4.837) A6(2.517,-2.303)
RJ45-18X15-8PS1
  round 3.2 hole 3.2 unplated: (-5.715,1.171) (5.715,1.171)
  round 1.524 hole 0.914: A1(4.445,-5.179) A2(3.175,-7.719) A3(1.905,-5.179) A4(0.635,-7.719) A5(-0.635,-5.179) A6(-1.905,-7.719) A7(-3.175,-5.179) A8(-4.445,-7.719)
SO-6_6X4-8P-1_27
  rect 1.905x0.635 smd: 1(3,-1.905) 2(3,-0.635) 3(3,0.635) 4(3,1.905) 5(-3,1.905) 6(-3,0.635) 7(-3,-0.635) 8(-3,-1.905)
SO-6X5-8P-1_27
  rect 2.032x0.635 smd: 1(2.997,-1.905) 2(2.997,-0.635) 3(2.997,0.635) 4(2.997,1.905) 5(-2.997,1.905) 6(-2.997,0.635) 7(-2.997,-0.635) 8(-2.997,-1.905)
SO-11_8X21-50P-0_8
  rect 1.524x0.406 smd: 1(5.512,-9.601) 2(5.512,-8.801) 3(5.512,-8.001) 4(5.512,-7.201) 5(5.512,-6.401) 6(5.512,-5.601) 7(5.512,-4.801) 8(5.512,-4) 9(5.512,-3.2) 10(5.512,-2.4) 11(5.512,-1.6) 12(5.512,-0.8) 13(5.512,0) 14(5.512,0.8) 15(5.512,1.6) 16(5.512,2.4) 17(5.512,3.2) 18(5.512,4) 19(5.512,4.801) 20(5.512,5.601) 21(5.512,6.401) 22(5.512,7.201) 23(5.512,8.001) 24(5.512,8.801) 25(5.512,9.601) 26(-5.512,9.601) 27(-5.512,8.801) 28(-5.512,8.001) 29(-5.512,7.201) 30(-5.512,6.401) 31(-5.512,5.601) 32(-5.512,4.801) 33(-5.512,4) 34(-5.512,3.2) 35(-5.512,2.4) 36(-5.512,1.6) 37(-5.512,0.8) 38(-5.512,0) 39(-5.512,-0.8) 40(-5.512,-1.6) 41(-5.512,-2.4) 42(-5.512,-3.2) 43(-5.512,-4) 44(-5.512,-4.801) 45(-5.512,-5.601) 46(-5.512,-6.401) 47(-5.512,-7.201) 48(-5.512,-8.001) 49(-5.512,-8.801) 50(-5.512,-9.601)
SO-11_8X22-54P-0_8
  rect 1.524x0.406 smd: 1(5.512,-10.399) 2(5.512,-9.601) 3(5.512,-8.801) 4(5.512,-8.001) 5(5.512,-7.201) 6(5.512,-6.401) 7(5.512,-5.601) 8(5.512,-4.801) 9(5.512,-4) 10(5.512,-3.2) 11(5.512,-2.4) 12(5.512,-1.6) 13(5.512,-0.8) 14(5.512,0) 15(5.512,0.8) 16(5.512,1.6) 17(5.512,2.4) 18(5.512,3.2) 19(5.512,4) 20(5.512,4.801) 21(5.512,5.601) 22(5.512,6.401) 23(5.512,7.201) 24(5.512,8.001) 25(5.512,8.801) 26(5.512,9.601) 27(5.512,10.399) 28(-5.512,10.399) 29(-5.512,9.601) 30(-5.512,8.801) 31(-5.512,8.001) 32(-5.512,7.201) 33(-5.512,6.401) 34(-5.512,5.601) 35(-5.512,4.801) 36(-5.512,4) 37(-5.512,3.2) 38(-5.512,2.4) 39(-5.512,1.6) 40(-5.512,0.8) 41(-5.512,0) 42(-5.512,-0.8) 43(-5.512,-1.6) 44(-5.512,-2.4) 45(-5.512,-3.2) 46(-5.512,-4) 47(-5.512,-4.801) 48(-5.512,-5.601) 49(-5.512,-6.401) 50(-5.512,-7.201) 51(-5.512,-8.001) 52(-5.512,-8.801) 53(-5.512,-9.601) 54(-5.512,-10.399)
SO-20X12-48P-0_5S1
  rect 1.905x0.305 smd: 1(9.804,-5.751) 2(9.804,-5.25) 3(9.804,-4.75) 4(9.804,-4.249) 5(9.804,-3.749) 6(9.804,-3.251) 7(9.804,-2.751) 8(9.804,-2.25) 9(9.804,-1.75) 10(9.804,-1.25) 11(9.804,-0.749) 12(9.804,-0.249) 13(9.804,0.249) 14(9.804,0.749) 15(9.804,1.25) 16(9.804,1.75) 17(9.804,2.25) 18(9.804,2.751) 19(9.804,3.251) 20(9.804,3.749) 21(9.804,4.249) 22(9.804,4.75) 23(9.804,5.25) 24(9.804,5.751) 25(-9.804,5.751) 26(-9.804,5.25) 27(-9.804,4.75) 28(-9.804,4.249) 29(-9.804,3.749) 30(-9.804,3.251) 31(-9.804,2.751) 32(-9.804,2.25) 33(-9.804,1.75) 34(-9.804,1.25) 35(-9.804,0.749) 36(-9.804,0.249) 37(-9.804,-0.249) 38(-9.804,-0.749) 39(-9.804,-1.25) 40(-9.804,-1.75) 41(-9.804,-2.25) 42(-9.804,-2.751) 43(-9.804,-3.251) 44(-9.804,-3.749) 45(-9.804,-4.249) 46(-9.804,-4.75) 47(-9.804,-5.25) 48(-9.804,-5.751)
SOT-23-3P
  rect 1.016x1.016 smd: 1(-0.889,-1.143) 2(0.889,-1.143) 3(0,1.143)
SOT-89-3P
  rect 1.143x1.524 smd: 1(-1.6,0) 3(1.6,0)
  custom 0.6x0.6 smd: 2(0,1.9)
SOT-143-4P
  rect 1.422x1.168 smd: 1(1.151,-0.749)
  rect 1.422x1.016 smd: 2(1.151,0.95) 3(-1.151,0.95) 4(-1.151,-0.95)
SOT-223-4P
  rect 1.524x1.143 smd: 1(3.15,-2.301) 2(3.15,0) 3(3.15,2.301)
  rect 1.981x3.81 smd: 4(-3.15,0)
SW-7_8X6_8-4P
  round 1.778 hole 1.016: 1(2.25,0) 2(-2.25,0)
  round 2.032 hole 1.27: 3(-3.5,2.5) 4(3.5,2.5)
SW-12_4X7_8-8P
  oval 2.311x1.702 hole 1.422x0.711: 1(-3.2,-1.45) 2(0,-1.45) 3(3.2,-1.45) 4(3.2,1.45) 5(0,1.45) 6(-3.2,1.45)
  round 2.007 hole 1.397: 7(-5.8,-3.2) 8(5.8,3.2)
T-17X15-12P
  oval 1.397x1.016 hole 0.762: 1(-6.6,-5.956) 2(-6.6,-4.255) 3(-6.6,-2.553) 4(-6.6,-0.851) 5(-6.6,0.851) 6(-6.6,2.553) 7(-6.6,4.255) 8(-6.6,5.956)
  round 1.524 hole 0.889: 9(6.6,5.956) 11(6.6,2.654) 14(6.6,-2.654) 16(6.6,-5.956)
TP_30
  round 0.762 smd: 1(0,0)
USB-16_5X12-4P
  round 1.295 hole 0.991: 1(1.25,6.741) 2(-1.25,6.741) 3(-1.25,4.74) 4(1.25,4.74)
  round 2.921 hole 2.311: S1(-6.02,2.029) S2(6.02,2.029)

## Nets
1.5V_AFE: C385.2 C386.2 C387.2 C388.2 CAP17.1(A) FB18.2 U1.22(VDD15A_USB) U1.34(VDD15A_P0) U1.58(VDDPLL) U1.61(VDDADC_1V5)
1.5V_PLL_E: C368.2 FB14.2 U1.42(VDD_PL)
3.3V_E: C372.2 C373.2 C374.2 C389.2 CAP14.1(A) FB15.2 Q307.3(E) U1.24(VDD3A_USB) U1.25(VDD3TX_USB) U1.29(VDD3A_P0) U1.35(VDDRG33_E)
+1V5: C358.2 C359.2 C360.2 C361.2 C362.2 C363.2 C364.2 C365.2 C366.2 C367.2 CAP8.1(A) CAP12.1(A) FB10.2 FB14.1 FB18.1 R432.1 U1.4(VDD(1.5V)#4) U1.17(VDD(1.5V)#17) U1.57(VDDD) U1.93(VDD(1.5V)#93) U1.103(VDD(1.5V)#103) U1.113(VDD(1.5V)#113) U1.139(VDD(1.5V)#139)
+3V3: C333.1 C341.2 C375.2 C376.2 C377.2 C378.2 C379.2 C380.2 C381.2 C392.2 C393.2 C394.2 C395.2 C396.2 C397.2 C398.2 C399.2 C400.2 C405.2 CAP20.1(A) CAP21.1(A) D22.2(C) FB15.1 FB17.1 J6.1 J11.1 R358.1 R359.1 R360.1 R361.1 R362.1 R365.1 R367.1 R369.2 R370.1 R372.1 R375.1 R376.1 R379.1 R380.1 R387.1 R388.1 R389.1 R391.1 R412.2 R413.2 R414.2 R417.1 R418.2 R419.2 R420.2 R421.2 R435.1 U1.3(VDDP(3.3V)#3) U1.18(VDDP(3.3V)#18) U1.46(VDDP(3.3V)#46) U1.54(VDDP(3.3V)#54) U1.92(VDDP(3.3V)#92) U1.105(VDDP(3.3V)#105) U1.109(VDDP(3.3V)#109) U1.140(VDDP(3.3V)#140) U14.2(OUT1) U14.4(OUT2) U15.3(VCC) U26.8(VCC) U27.1(VDD1) U27.3(VDDQ1) U27.9(VDDQ4) U27.14(VDD3) U27.27(VDD2) U27.43(VDDQ2) U27.49(VDDQ3) U28.1(VDD6) U28.7(VDD5) U28.13(VDD3) U28.25(VDD4) U28.38(VDD2) U28.44(VDD1) U29.37(VCC) U30.4(VDD)
+5V: C323.1 C324.1 C370.2 C404.2 CAP3.1(A) CAP18.1(A) D20.4(C) FB20.1 FB21.1 L1.2 R337.1 R393.2
DGND: C320.2 C321.2 C322.2 C323.2 C324.2 C325.2 C326.2 C327.2 C328.2 C329.2 C331.2 C333.2 C338.2 C339.2 C340.1 C341.1 C342.2 C343.1 C344.1 C352.2 C353.2 C354.2 C355.1 C358.1 C359.1 C360.1 C361.1 C362.1 C363.1 C364.1 C365.1 C366.1 C367.1 C368.1 C369.1 C370.1 C371.1 C372.1 C373.1 C374.1 C375.1 C376.1 C377.1 C378.1 C379.1 C380.1 C381.1 C382.1 C383.1 C384.1 C385.1 C386.1 C387.1 C388.1 C391.1 C392.1 C393.1 C394.1 C395.1 C396.1 C397.1 C398.1 C399.1 C400.1 C404.1 C405.1 CAP1.2(C) CAP2.2(C) CAP3.2(C) CAP4.2(C) CAP5.2(C) CAP6.2(C) CAP8.2(C) CAP12.2(C) CAP13.2(C) CAP14.2(C) CAP16.2(C) CAP17.2(C) CAP18.2(C) CAP19.2(C) CAP20.2(C) CAP21.2(C) CAP22.2(C) D14.1(A) D15.1(A) D16.1(A) D17.1(A) D18.1(A) D19.1(A) D20.1(A) J6.2 J8.1(GND1) J8.S1(GND2) J8.S2(GND3) J11.4 Q304.2(E) R338.1 R349.1 R364.1 R366.1 R368.1 R371.1 R373.1 R390.1 R392.2 R409.2 R423.2 R438.1 S1.2 S1.3 S1.4 U1.23(VSS3A_USB) U1.28(VSS3TX_USB) U1.82(VSSLD_1) U1.85(VSSLD_2) U1.145(NC) U11.2(SWE) U11.4(GND) U12.2(SWE) U12.4(GND) U14.1(ADJ/GND) U15.1(VSS) U26.4(GND) U27.6(VSSQ1) U27.12(VSSQ4) U27.28(VSS1) U27.41(VSS2) U27.46(VSSQ2) U27.52(VSSQ3) U27.54(VSS3) U28.4(VSSQ4) U28.10(VSSQ3) U28.26(VSS2) U28.41(VSSQ2) U28.47(VSSQ1) U28.50(VSS1) U29.27(VSS1) U29.46(VSS2) U30.1(GND)
V1.8_SENSE: R411.2 U1.38(VFB1V8)
VDD3.3_AFE: C382.2 C383.2 C384.2 CAP16.1(A) FB17.2 U1.68(VDDRX_3V3) U1.75(VDDTX_3V3#75) U1.88(VDDTX_3V3#88)
VDD_1.8V: C391.2 CAP19.1(A) FB13.2 Q307.2(C) R411.1
VDD_5V: C369.2 C371.2 CAP13.1(A) D18.2(C) D19.2(C) FB20.2 U1.80(VDDLD_5V_1) U1.87(VDDLD_5V_2)
VIN: C320.1 C321.1 C325.1 C326.1 CAP1.1(A) CAP2.1(A) CAP4.1(A) CAP5.1(A) D23.2(C) R329.2 R330.2 R331.2 R339.2 R340.2 R341.2 R342.2 R424.1 R436.2 U11.6(VCC) U12.6(VCC)
C1M: C334.2 U1.77(C1M)
C1P: C334.1 U1.76(C1P)
C2M: C335.2 U1.62(C2M)
C2P: C335.1 U1.63(C2P)
C3M: C336.2 U1.64(C3M)
C3P: C336.1 U1.65(C3P)
CONTROL_1.8V: C389.1 Q307.1(BASE) U1.39(VCTRL1.8V)
CREFM: C337.2 U1.73(CREFM)
CREFP: C337.1 U1.74(CREFP)
DATA: LED3.2(C) U1.15(GPIO(2)/LED_D/ADSL_LED(1)/L1LED)
DG_SENSE: R423.1 R424.2 U1.66(TPM/DG_SENSE)
EJTAG_TCK: R379.2 U1.53(TCK/EJ_TCK)
EJTAG_TDI: R388.2 U1.52(TDI/EJ_TDI/GPIO(16))
EJTAG_TDO: R365.2 R366.2 R387.2 U1.49(TDO/EJ_TDO/TESTMODE(0))
EJTAG_TMS: R380.2 U1.50(TMS/EJ_TMS/GPIO(18))
EJTAG_TRST: R364.2 U1.51(TRST/EJ_TRST)
ETHERNET: LED4.2(C) U1.16(GPIO(3)/LED_SH/L1LED_LINKACT/EB)
FFRING: R381.2 R382.2 R385.2 R427.1 T5.6
FFTIP: R381.1 R382.1 R384.2 R428.1 T5.7
FL_A15: U1.112(FL_A[15]/RMII_RXD(0)/MII_RXD(0)) U29.2(A14)
FL_A16: U1.111(FL_A[16]/MII_TXCLK/SDIO_D(1)/GP) U29.1(A15)
FL_A17: U1.110(FL_A[17]/ALE/MII_TXD(3)/SDIO_D() U29.48(A16)
FL_A18: U1.108(FL_A[18]/RMII_RXD(1)/SE/MII_RXD) U29.17(A17)
FL_A19: U1.107(FL_A[19]/PRE/RMII_REFCLK/MII_RX) U29.16(A18)
FL_A20: R415.1 R416.2 U1.106(FL_A[20]/ND_WP_N/RMII_RXDVCRS/M)
FL_A21: U1.104(FL_A[21]/ND_RD_BY_N/MII_RXD(2)/) U29.10(A20)
FL_A22: U1.102(FL_A[22]/ND_CLE/SPI_CS(3)/CLK_O) U29.13(A21)
FL_CS0: R372.2 R373.2 U1.95(FL_CS(0)/ND_CS#/SPI_CS(2)/SDIO_) U29.26(C\E\)
FL_CS1: R389.2 R390.2 U1.96(FL_CS(1)/ND_CS#/CLK_OUT(2)/JTAG)
FL_RD_N/ND_RD_N: U1.100(FL_RD_N/ND_RD_N/MII_TXD(2)/EXIN) U29.28(O\E\)
FL_RD_WR_N/ND_WR_N: U1.94(FL_RD_WR_N/ND_WR_N/MII_RXD(3)/S) U29.11(W\E\)
FLASH_RY/BY#: R419.1 U29.15(RY/B\Y\)
GPIO1: LED2.2(C) R367.2 R368.2 U1.14(GPIO(1)/LED_ST/ADSL_LED(0)/EBU_)
GPIO13: LED1.1(C1) U1.97(WAIT_N/RMII_TXEN/MII_TXEN/DCL_C)
GPIO24: LED1.3(C2) U1.98(FL_BC(1)/EBU_DT/MII_MDIO/GPIO(2)
IS_BYTE: R418.1 U29.47(B\Y\T\E\)
POR_IN: R413.1 U1.91(POR_IN) U15.2(RESET) U30.2(R\E\S\E\T\#\)
POR_OUT: R414.1 U1.89(HRST_N/POR_OUT) U29.12(R\E\S\E\T\)
RD+: R405.1 T4.6(RD+) U1.31(RXP)
RD-: R406.1 T4.8(RD-) U1.30(RXN)
RESET_DEFAULT: R356.2 U1.90(GPIO(0)/EXIN(2)/RMII_TXD(0)/MII)
RTX: R409.1 U1.36(RTX)
SD_ADDR0: TP1.1 U1.9(SD_ADDR(0)   /FL_A[0]) U27.23(A0) U28.21(A0)
SD_ADDR1: U1.10(SD_ADDR(1)   / FL_A[1]) U27.24(A1) U28.22(A1) U29.25(A0)
SD_ADDR2: U1.11(SD_ADDR(2)   /FL_A[2]) U27.25(A2) U28.23(A2) U29.24(A1)
SD_ADDR3: U1.12(SD_ADDR(3)   / FL_A[3]) U27.26(A3) U28.24(A3) U29.23(A2)
SD_ADDR4: U1.2(SD_ADDR(4)   / FL_A[4]) U27.29(A4) U28.27(A4) U29.22(A3)
SD_ADDR5: U1.1(SD_ADDR(5)   / FL_A[5]) U27.30(A5) U28.28(A5) U29.21(A4)
SD_ADDR6: U1.144(SD_ADDR(6)   / FL_A[6]) U27.31(A6) U28.29(A6) U29.20(A5)
SD_ADDR7: U1.143(SD_ADDR(7)   /FL_A[7]) U27.32(A7) U28.30(A7) U29.19(A6)
SD_ADDR8: U1.142(SD_ADDR(8)   / FL_A[8]) U27.33(A8) U28.31(A8) U29.18(A7)
SD_ADDR9: U1.141(SD_ADDR(9)   / FL_A[9]) U27.34(A9) U28.32(A9) U29.8(A8)
SD_ADDR10: U1.8(SD_ADDR(10) / FL_A[10]) U27.22(A10/AP) U28.20(A10) U29.7(A9)
SD_ADDR11: U1.138(SD_ADDR(11) / FL_A[11]) U27.35(A11) U29.6(A10)
SD_ADDR12: U1.137(SD_ADDR(12) / FL_A[12]) U27.36(A12) U29.5(A11)
SD_BA0: U1.6(SD_BA(0)) U27.20(BA0) U28.19(BA)
SD_BA1: U1.7(SD_BA(1)) U27.21(BA1)
SD_CAS_N_R: U1.124(SD_CAS_N) U27.17(CAS) U28.16(C\A\S\)
SD_CKE: R391.2 U1.136(SD_CKE) U27.37(CKE) U28.34(CKE)
SD_CLK_O_R: R431.1 U27.38(CLK) U28.35(CLK)
SD_CS0_N: U1.5(SD_CS0_N) U27.19(CS) U28.18(C\S\)
SD_DQ0: U1.114(SDR_DQ(0)/FL_DQ[0]) U27.2(DQ0) U28.2(DQ0) U29.29(DQ0)
SD_DQ1: U1.115(SDR_DQ(1)/FL_DQ[1]) U27.4(DQ1) U28.3(DQ1) U29.31(DQ1)
SD_DQ2: U1.116(SDR_DQ(2)/FL_DQ[2]) U27.5(DQ2) U28.5(DQ2) U29.33(DQ2)
SD_DQ3: U1.117(SDR_DQ(3)/FL_DQ[3]) U27.7(DQ3) U28.6(DQ3) U29.35(DQ3)
SD_DQ4: U1.118(SDR_DQ(4)/FL_DQ[4]) U27.8(DQ4) U28.8(DQ4) U29.38(DQ4)
SD_DQ5: U1.119(SDR_DQ(5)/FL_DQ[5]) U27.10(DQ5) U28.9(DQ5) U29.40(DQ5)
SD_DQ6: U1.120(SDR_DQ(6)/FL_DQ[6]) U27.11(DQ6) U28.11(DQ6) U29.42(DQ6)
SD_DQ7: U1.121(SDR_DQ(7)/FL_DQ[7]) U27.13(DQ7) U28.12(DQ7) U29.44(DQ7)
SD_DQ8: U1.133(SDR_DQ(8)/FL_DQ[8]) U27.42(DQ8) U28.39(DQ8) U29.30(DQ8)
SD_DQ9: U1.132(SDR_DQ(9)/FL_DQ[9]) U27.44(DQ9) U28.40(DQ9) U29.32(DQ9)
SD_DQ10: U1.131(SDR_DQ(10)/FL_DQ[10]) U27.45(DQ10) U28.42(DQ10) U29.34(DQ10)
SD_DQ11: U1.130(SDR_DQ(11)/FL_DQ[11]) U27.47(DQ11) U28.43(DQ11) U29.36(DQ11)
SD_DQ12: U1.129(SDR_DQ(12)/FL_DQ[12]) U27.48(DQ12) U28.45(DQ12) U29.39(DQ12)
SD_DQ13: U1.128(SDR_DQ(13)/FL_DQ[13]) U27.50(DQ13) U28.46(DQ13) U29.41(DQ13)
SD_DQ14: U1.127(SDR_DQ(14)/FL_DQ[14]) U27.51(DQ14) U28.48(DQ14) U29.43(DQ14)
SD_DQ15: U1.126(SDR_DQ(15)/FL_DQ[15]) U27.53(DQ15) U28.49(DQ15) U29.45(DQ15/A-1)
SD_DQM0: U1.122(SD_DQM(0)/ FL_A[13]) U27.15(LDQM) U28.14(LDQM) U29.4(A12)
SD_DQM1: U1.134(SD_DQM(1)/ FL_A[14]) U27.39(UDQM) U28.36(UDQM) U29.3(A13)
SD_RAS_N_R: U1.125(SD_RAS_N) U27.18(RAS) U28.17(R\A\S\)
SD_WE_N: U1.123(SD_WE_N) U27.16(WE) U28.15(W\E\)
SPI_CLK: U1.44(GPIO(10)/SPI_CLK/RMII_REFCLK/JT) U26.6(CLK)
SPI_CS1: R422.1 U1.48(GPIO(7)/SPI_CS(1)/RMII_CRSDV/JT)
SPI_DIN: U1.47(GPIO(8)/SPI_DIN/RMII_RXD(1)/JTA) U26.5(DI)
SPI_DOUT: U1.45(GPIO(9)/SPI_DOUT/RMII_RXD(0)/JT) U26.2(DO)
TD+: R403.2 T4.1(TD+) U1.33(TXP)
TD-: R404.2 T4.3(TD-) U1.32(TXN)
TP45: J9.A4(P4) J9.A5(P5) R401.1
TP78: J9.A7(P7) J9.A8(P8) R400.1
TPRXN: J9.A2(TX-) T4.9(RX-)
TPRXP: J9.A1(TX+) T4.11(RX+)
TPTXN: J9.A6(RX-) T4.14(TX-)
TPTXP: J9.A3(RX+) T4.16(TX+)
TRING: D18.3(AC) R425.1 T5.8
TTIP: D19.3(AC) R426.1 T5.5
UART_RX: R397.2 U1.20(UART_RX1/GPT(1)/GPIO(5)/MII_RXE)
UART_TX: R374.2 U1.19(UART_TX1/EXIN(0)/GPIO(6)/MII_CO)
USB: LED5.2(C) R370.2 R371.2 U1.99(FL_BC(0)/MII_MDC/GPIO(27)/STRAP)
USB_DM: D20.3(CA) J8.3(D-) R433.1 T6.3
USB_DP: D20.2(AC) J8.2(D+) R434.1 T6.2
USB_RREF: R392.1 U1.21(USB_RREF)
VCTRL1.5: U1.40(VCTRL1.5)
VREF: C355.2 U1.37(VREF)
WAN_FFRING: R427.2 U1.79(WAN_FFRING)
WAN_FFTIP: R428.2 U1.78(WAN_FFTIP)
WAN_HYBRING: C832.1 R430.2 U1.69(WAN_HYBRING)
WAN_HYBTIP: C832.2 R429.2 U1.70(WAN_HYBTIP)
WAN_RRING: C347.1 R377.1 U1.71(WAN_RRING)
WAN_RTIP: C347.2 R378.1 U1.72(WAN_RTIP)
WAN_TRING: R386.2 R425.2 U1.84(WAN_TRING1) U1.86(WAN_TRING2)
WAN_TTIP: R383.2 R426.2 U1.81(WAN_TTIP1) U1.83(WAN_TTIP2)
WAN_XTAL1: C339.1 U1.59(WAN_XTAL1) Y3.1
WAN_XTAL2: R357.1 U1.60(WAN_XTAL2)
N24553116: C318.2 FB8.1 J5.2(SHIELDA) J5.3(SHIELDB)
N24553123: C318.1 FB7.1 J5.1(CENTER)
N24553218: C319.1 FB7.2 SW1.2 SW1.5
N24553231: C319.2 D12.1(A) D14.2(C) FB8.2 R438.2
N24553775: SW1.1 SW1.6
N24553814: D13.1(A) D15.2(C) R437.1 SW1.3 SW1.4
N24560058: D12.2(C) D13.2(C) D23.1(A) R436.1 R437.2
N24568861: Q305.3(E) R329.1 R330.1 R331.1 R332.1 U11.7(IPK)
N24570515: R333.1 U11.1(SWC) U11.8(DRI)
N24571646: Q305.1(BASE) R332.2 R333.2
N24576177: C322.1 R336.2 U11.3(TC)
N24577143: D16.2(C) L1.1 Q305.2(C) R336.1
N24581993: R337.2 R338.2 U11.5(FB)
N24591362: Q306.3(E) R339.1 R340.1 R341.1 R342.1 R343.1 U12.7(IPK)
N24592746: Q306.1(BASE) R343.2 R344.2
N24593053: R344.1 U12.1(SWC) U12.8(DRI)
N24596017: C327.1 R347.2 U12.3(TC)
N24596365: D17.2(C) L2.1 Q306.2(C) R347.1
N24598462: C328.1 C329.1 CAP6.1(A) FB10.1 L2.2 R348.1
N24599371: R348.2 R349.2 U12.5(FB)
N24616723: C331.1 FB21.2 U14.3(INPUT)
N24643911: C340.2 R356.1 R412.1 S1.1
N24649929: J6.4 J11.2 R397.1 R435.2
N24681692: C338.1 R357.2 Y3.2
N24688074: LED4.1(A) R361.2
N24688185: LED5.1(A) R362.2
N24688407: LED3.1(A) R360.2
N24690395: LED2.1(A) R359.2
N24766052: R369.1 U1.67(TPP/OC_SENSE)
N24768447: C346.1 C348.2 T5.4
N24768604: T5.2 T5.3
N24769563: C346.2 C349.2 T5.1
N24772143: C348.1 R377.2
N24772316: C349.1 R378.2
N24790501: C345.1 T5.14
N24791080: C345.2 T5.11
N24805096: C353.1 J10.A3(RING1-) RV1.2 RV2.2 T5.9
N24805705: C352.1 J10.A4(TIP3+) RV1.1 RV2.1 T5.16
N24814618: C350.1 R385.1 R386.1
N24814840: C351.1 R383.1 R384.1
N24819336: C350.2 R430.1
N24819791: C351.2 R429.1
N24827024: R431.2 U1.135(SD_CLK_O)
N24844121: R416.1 R417.2 U29.14(W\P\/ACC)
N24844282: R415.2 U29.9(A19)
N24965644: J8.4(VCC) R393.1
N25062355: J6.3 J11.3 R374.1
N25093250: R398.2 T4.15(TCM)
N25093296: R399.2 T4.10(RCM)
N25094967: R398.1 R399.1 R402.2
N25097039: C344.2 FB13.1 R407.1 R408.1 T4.2(TC) T4.7(RC)
N25099977: C342.1 R403.1 R404.1 R407.2
N25100585: C343.2 R405.2 R406.2 R408.2
N25501507: LED1.2(A) R358.2
N25576572: R420.1 U26.7(H\O\L\D\)
N25585764: R421.1 U26.3(W\P\)
N25586045: R422.2 U26.1(C\S\)
N25936981: CAP23.1(A) D22.1(A) U30.3(M\R\#\)
N25958136: CAP22.1(A) Q304.1(BASE) R376.2
N25963368: CAP23.2(C) Q304.3(C) R375.2
N26013339: R432.2 U1.41(VFB1V5)
N26031302: R433.2 T6.4 U1.27(USB_DM)
N26031664: R434.2 T6.1 U1.26(USB_DP)
N26189415: C354.1 R400.2 R401.2 R402.1

Pads without a net: J10 A1 A2 A5 A6; SW1 7 8; T4 4 5 12 13; U1 13 43 55 56 101; U27 40; U28 33 37

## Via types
v1: diameter 0.711, hole 0.406, TOP to BOTTOM, 11 vias
v2: diameter 0.61, hole 0.305, TOP to BOTTOM, 272 vias

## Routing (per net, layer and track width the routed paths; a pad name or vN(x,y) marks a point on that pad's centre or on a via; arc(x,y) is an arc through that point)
1.5V_AFE: length 51.4
  TOP w0.254: C386.2 68.27,20.1 U1.61 68.27,23.5 ; C388.2 66.77,20.08 U1.58 66.77,23.88 ; C387.2 52.7,24.89 U1.34 55.24,24.89 v2(55.5,25.15) ; v2(55.75,31.24) 55.4,30.89 U1.22 52.85,30.89 C385.2
  TOP w0.508: FB18.2 46.95,31.26 v2(45.96,31.26) CAP17.1 ; 66.77,23.88 66.8,23.9 66.8,24.51 ; 66.8,24.51 67.97,24.51 68.27,24.21 68.27,23.5 ; 66.8,24.51 59.82,24.51 v2(59.18,25.15) v2(59.18,31.24)
  BOTTOM w0.406: v2(55.5,25.15) v2(59.18,25.15)
  BOTTOM w0.508: v2(59.18,31.24) v2(55.75,31.24) 45.97,31.24 v2(45.96,31.26)
1.5V_PLL_E: length 7.4
  TOP w0.254: C368.2 58.17,16.75 58.17,17.86 58.77,18.47 U1.42
  TOP w0.508: FB14.2 56.35,16.37 C368.2
3.3V_E: length 30.6
  TOP w0.254: C372.2 52.74,27.39 U1.29 56.04,27.39 56.21,27.56 ; U1.24 52.75,29.89 52.57,29.71 C374.2 52.64,29.39 U1.25 55.63,29.39 ; C373.2 53.08,24.39 U1.35 56.21,24.39
  TOP w0.508: 55.63,29.39 56.21,28.81 56.21,24.2 53.47,21.46 51.94,21.46
  TOP w0.533: 50.16,20.79 Q307.3 51.13,20.01 ; 42.11,23.19 FB15.2 42.76,22.48 ; CAP14.1 45.54,24.4 ; CAP14.1 44.58,23.43 ; CAP14.1 43.61,24.4 ; 52.46,20.43 C389.2 51.98,19.94
+1V5: length 147.7
  TOP w0.254: C363.2 66.27,20.67 U1.57 66.27,23.13 65.66,23.75 v1(58.42,23.75) ; C366.2 71.78,44.74 U1.113 71.78,41.37 ; C367.2 53.47,33.39 U1.17 55.85,33.39 v2(55.88,33.36) ; U1.103 76.64,38.89 v2(76.99,39.24) 77.14,39.4 79.79,39.4 C365.2 ; C358.2 58.42,44.83 58.77,44.48 U1.139 58.77,41.37 ; U1.93 76.69,33.89 76.96,34.16 C364.2 ; C359.2 52.58,39.89 U1.4 56.42,39.89
  TOP w0.508: v2(45.97,33.36) 46.49,32.84 FB18.1 ; v1(58.42,23.75) 58.29,23.88 v2(58.29,33.36) 58.29,34.29 56.42,36.16 v2(56.42,41.37) 71.78,41.37 71.78,39.22 v2(72.26,38.73) 72.39,38.61 v2(72.39,35.04) ; R432.1 57.91,18.54 v1(57.66,18.29) ; 53.59,16.38 C360.2 ; C364.2 v2(77.61,35.04)
  TOP w0.533: 34.26,11.71 CAP8.1 ; CAP8.1 35.43,10.54 ; CAP8.1 36.6,11.71 ; CAP8.1 35.43,12.88 ; C361.2 33.4,8.6 ; C361.2 32.91,8.12 ; C361.2 33.9,8.12 ; 34.18,8.12 C362.2 ; C362.2 34.67,8.6 ; C362.2 35.17,8.12 ; 32.54,8.38 FB10.2 31.88,9.35
  TOP w0.762: v1(57.66,18.29) 56.79,17.42 55.24,17.42 54.92,17.1 FB14.1 53.59,16.38 53.45,16.24 ; 53.45,16.24 C360.2 ; 53.45,16.24 53.45,15.35 53.34,15.24 38.1,15.24 37.34,14.48 37.34,12.57
  BOTTOM w0.508: v2(76.99,39.24) 76.48,38.73 v2(72.26,38.73) ; CAP12.1 55.23,44.97 56.42,43.78 v2(56.42,41.37) ; v2(45.97,33.36) v2(55.88,33.36) v2(58.29,33.36) ; v2(77.61,35.04) v2(72.39,35.04)
  BOTTOM w0.762: v1(58.42,23.75) 58.42,22.35 57.66,21.59 v1(57.66,18.29)
+3V3: length 460.9
  TOP w0.152: C378.2 57.81,45.76 57.81,47.85 v2(57.28,48.39) ; R391.1 v2(58.93,48.9)
  TOP w0.254: C381.2 53.2,40.39 U1.3 55.37,40.39 55.75,40.77 55.75,41.66 56.18,42.08 v2(58.17,42.08) 58.27,42.19 U1.140 58.27,44.23 C378.2 ; C379.2 60.96,20.64 60.77,20.83 U1.46 60.77,23.05 60.96,23.24 64.52,23.24 64.77,22.98 U1.54 64.77,20.31 C377.2 ; C333.1 81.37,33.74 81.22,33.59 76.97,33.59 76.76,33.39 U1.92 ; C392.2 73.78,44.2 U1.109 ; v2(56.39,32.64) 55.63,32.64 55.38,32.89 U1.18 53.34,32.89 53.09,33.15 C380.2 ; C393.2 77.5,39.89 U1.105
  TOP w0.305: U29.37 83.43,46.47 C341.2 ; R369.2 72.29,15.88 75.31,15.88 77.09,14.1 ; R420.2 46.23,8.76 ; C341.2 83.55,45.96 83.31,45.72 v2(79.5,45.72) ; C341.2 R418.2
  TOP w0.406: J11.1 39.88,48.13 39.22,47.47 v1(39.22,40.77) ; J11.1 C394.2 ; J11.1 J6.1 ; U27.14 U28.13 C400.2 ; U27.1 72.5,65.55 71.7,66.34 U28.1 71.7,68.77 ; U27.9 v2(66.1,65.79) ; U28.7 66.9,68.75 C399.2 ; C396.2 52.5,68.8 U28.25 52.5,66.47 51.7,65.67 U27.27 ; U27.49 68.5,51.75 C397.2 ; v2(67.06,54.74) 66.9,54.89 U28.44 ; v2(63.5,54.74) 63.7,54.53 U27.43 63.7,51.73 C395.2 ; U28.38 v2(62.1,54.74) ; U27.3 70.9,63.33 v2(71.12,63.12)
  TOP w0.508: v1(57.28,36.45) 59.05,34.67 v2(59.05,32.64) ; R376.1 92.55,34.29 87.38,34.29 ; FB17.1 80.38,16.8 C375.2 80.38,14.47 80.01,14.1 77.09,14.1 76.2,13.21 v2(76.2,5.97) ; 81.37,36.74 R389.1 v2(82.42,37.85) ; 81.37,36.74 U15.3 v2(81.92,34.67) 81.41,34.16 C333.1 ; 81.37,36.74 81.28,36.83 R372.1 ; R375.1 87.54,34.45 87.38,34.29 ; R375.1 86.38,35.56 R413.2 ; R375.1 87.54,37.44 D22.2 88.01,39.75 87.5,40.26 84.91,40.26 U30.4 82.42,41.41 81.91,40.89 v2(79.12,40.89) 77.99,40.89 77.61,40.51 C393.2 ; 62.9,16.55 62.9,19.05 R380.1 ; 62.9,16.55 62.77,16.42 R387.1 R365.1 v2(61.21,15.49) 59.94,14.22 59.94,13.11 v2(59.97,13.08) 59.94,13.06 v2(59.94,7.49) v2(48.26,7.49) 48.26,7.51 48.15,7.62 C405.2 ; 62.9,16.55 62.9,15.33 63.32,14.91 64.05,14.91 64.47,15.33 64.47,15.95 64.93,16.42 R388.1 R379.1 ; v2(48.26,5.17) R359.1 R358.1 ; 87.38,34.29 v2(84.07,34.29) 83.63,33.84 v2(83.63,30.82) ; R370.1 79.38,38.86 v2(79.5,38.73) ; R412.2 81.1,30.99 v2(81.08,31.01) R414.2 ; C379.2 v2(60.21,20.05) ; C398.2 71.7,68.77 ; C398.2 73.4,68.85 ; C398.2 C399.2 C400.2 58.94,68.85 58.17,69.62 54.64,69.62 53.86,68.85 C396.2 ; v2(39.37,13.84) 40.51,12.7 v2(40.51,8.76) ; 73.4,68.85 74.04,68.21 v2(74.04,63.12) ; 73.4,68.85 CAP20.1 81.38,71.25 R419.2 81.67,70.96 R417.1 ; U26.8 48.18,8.8 C405.2 ; C392.2 75.68,45.1 v2(75.82,44.96) 75.83,44.96 76.85,43.94 v2(79.12,43.94) ; C405.2 v2(42.29,8.76) ; R367.1 R360.1 v2(59.94,5.17) R361.1 R362.1 74.35,5.17 v2(74.51,5.33) ; U27.49 68.5,54.47 v2(68.24,54.74) ; R421.2 57.73,12.83 v2(57.99,13.08)
  TOP w0.533: U14.2 31.62,31.17 ; U14.2 31.62,29.24 ; U14.2 32.4,30.2 ; U14.4 33.73,23.9 ; U14.4 31.62,25.1 ; U14.4 29.51,23.9 ; U14.4 31.62,22.71 ; CAP21.1 39.19,24.53 ; CAP21.1 38.23,23.56 ; CAP21.1 37.26,24.53 ; C376.2 38.23,22.44 ; C376.2 38.72,21.96 ; C376.2 37.73,21.96 ; 40.04,22.48 FB15.1 40.69,23.19
  TOP w0.762: v1(52.58,35.69) 50.45,35.69 v1(48.64,37.5) ; v1(39.22,40.77) 39.22,39.14 40.86,37.5 R435.1 v1(44.7,37.5) ; v1(57.28,36.45) 57.28,39.62 v2(58.17,40.51) v1(70.87,40.51) ; v1(31.62,40.77) 31.62,35.56 39.75,27.43 39.75,25.02 ; v2(76.58,47.88) 76.58,49.53 77.72,50.67 v2(77.72,56.64) 77.72,58.42 74.04,62.1 v2(74.04,63.12)
  BOTTOM w0.152: v2(57.28,48.39) 57.78,48.9 v2(58.93,48.9)
  BOTTOM w0.508: CAP21.1 38.23,14.99 v2(39.37,13.84) ; v2(58.17,42.08) v2(58.17,40.51) ; v2(82.42,37.85) 81.66,37.85 80.77,38.73 v2(79.5,38.73) ; v2(59.94,5.17) v2(59.94,7.49) ; v2(84.07,34.29) 83.69,34.67 v2(81.92,34.67) ; v2(56.39,32.64) v2(59.05,32.64) ; v2(66.1,65.79) 66.1,64.83 66.67,64.26 68.71,64.26 69.85,63.12 v2(71.12,63.12) v2(74.04,63.12) ; v2(61.21,15.49) 61.21,19.05 v2(60.21,20.05) ; v2(81.08,31.01) 81.27,30.82 v2(83.63,30.82) ; v2(74.51,5.33) 75.15,5.97 v2(76.2,5.97) ; v2(77.72,56.64) 68.96,56.64 68.24,55.92 v2(68.24,54.74) v2(67.06,54.74) v2(63.5,54.74) v2(62.1,54.74) ; v2(79.12,40.89) v2(79.12,43.94) 79.12,45.34 v2(79.5,45.72) ; v2(48.26,7.49) v2(48.26,5.17) ; v2(57.99,13.08) v2(59.97,13.08) ; v2(40.51,8.76) v2(42.29,8.76)
  BOTTOM w0.762: v2(76.58,47.88) 76.58,45.72 v2(75.82,44.96) 71.37,40.51 v1(70.87,40.51) ; v1(44.7,37.5) v1(48.64,37.5) ; v1(31.62,40.77) v1(39.22,40.77) ; v1(57.28,36.45) 56.52,35.69 v1(52.58,35.69)
+5V: length 174.2
  TOP w0.254: 27.18,38.73 27.18,58.42 25.4,60.2 R337.1
  TOP w0.508: v2(68.71,73.03) 68.71,79.02 R393.2 69.19,79.5 73.86,79.5 D20.4
  TOP w0.533: 21.17,38.6 L1.2 ; L1.2 21.17,40.91 ; L1.2 22.33,39.75 ; 23.24,36.77 C324.1 22.75,36.28 ; C323.1 26.5,35.42 ; C323.1 26.5,34.43 ; C323.1 26.99,34.92 ; 24.88,36.31 C404.2 24.38,36.79 ; CAP3.1 29.49,38 ; CAP3.1 28.32,39.17 ; CAP3.1 28.32,36.83 ; CAP3.1 27.15,38 ; 27.09,33.78 FB21.1 27.74,34.49
  TOP w0.762: v1(31.11,43.69) 30.1,42.67 30.1,38.99 ; FB20.1 95.52,40.3 C370.2 95.52,42.29 CAP18.1 92.36,45.45 92.36,63.88 92.33,63.92 92.33,64.01 90.17,66.17 90.17,70.61 87.76,73.03 v2(70.87,73.03) ; v1(38.48,43.69) 38.48,50.63 48.9,61.05 48.9,70.87 51.05,73.03 v2(68.71,73.03)
  BOTTOM w0.762: v2(68.71,73.03) v2(70.87,73.03) ; v1(38.48,43.69) v1(31.11,43.69)
DGND: length 126.1
  TOP w0.152: v2(78.9,56.39) v2(78.9,49.95)
  TOP w0.254: U1.82 v2(74.55,28.39) ; U1.85 v2(74.55,29.89)
  TOP w0.305: v2(78.9,49.95) 78.44,49.48 U29.27 ; v2(88.14,49.78) 87.93,49.58 U29.46
  TOP w0.406: U27.12 v2(63.7,63.12) ; U27.46 66.1,52.13 v2(65.91,51.94) ; v2(64.52,65.79) 64.5,65.8 U28.10 ; U27.41 62.1,52.2 v2(62.36,51.94) ; U28.50 71.7,55.17 v2(72.24,54.64) 72.5,54.37 U27.54 ; C382.1 72.01,19.05 72.26,18.8 v2(72.77,18.8) ; U28.41 64.5,57.26 v2(64.64,57.4) ; U28.47 v2(69.3,57.4) ; v2(51.7,51.94) U27.28 51.7,54.24 52.5,55.04 U28.26 ; U27.6 v2(68.5,63.2) ; U28.4 v2(69.3,65.82) ; U27.52 v2(70.9,51.98)
  TOP w0.508: v2(60.07,15.49) 60.2,15.62 R366.1 ; R349.1 15.24,33.91 v2(15.11,34.04) ; C364.1 79.38,34.16 v2(79.5,34.29) ; C343.1 v2(33.62,66.8) ; C377.1 C363.1 ; C363.1 v2(65.66,18.29) ; C363.1 C388.1 v2(66.8,18.29) ; U26.4 v2(52.45,14.1) ; C360.1 v2(51.56,16.38) ; C391.1 v2(30.48,81.15) ; R390.1 v2(82.22,38.86) ; C342.2 v2(33.64,73.04) ; v2(79.38,40.02) 79.36,40.01 C393.1 ; v2(15.11,60.45) 15.78,60.45 R338.1 ; C361.1 v2(32.42,7.15) ; C372.1 v2(50.67,27.56) ; C394.1 v2(41.87,51.27) ; C344.1 v2(33.53,78.49) ; v2(79.38,31.88) 79.25,32 C383.1 ; C386.1 68.33,18.41 v2(68.45,18.29) ; v2(50.67,29.46) C374.1 C385.1 ; C385.1 51.59,30.62 R392.2 ; C385.1 50.8,30.61 v2(50.67,30.48) ; C395.1 v2(63.75,49.78) ; C387.1 v2(50.67,25.02) ; R373.1 v2(79.38,35.81) ; R423.2 69.2,16.14 C338.2 v2(70.1,15.11) ; C368.1 v2(57.78,14.61) ; C322.2 v2(26.02,58.53) ; v2(50.57,34.42) 51.6,34.42 C367.1 C380.1 ; U11.4 v2(21.46,58.8) ; C369.1 v2(79.38,30.86) ; C331.2 v2(27.83,30.99) ; U11.2 v2(21.46,56.26) ; R368.1 v2(49.95,5.17) ; C329.2 v2(29.07,7.12) ; C327.2 26.02,32.02 v2(25.78,32.26) ; C333.2 v2(80.4,35.04) ; C320.2 v2(13.47,33.03) ; C405.1 v2(50.16,8.76) ; C358.1 v2(58.42,47.12) ; C362.1 v2(35.65,7.15) ; v2(74.42,75.06) 74.42,75.8 D20.1 75.44,75.82 v2(75.44,75.06) ; C365.1 v2(82.22,40.01) ; R364.1 63.75,16.29 v2(63.75,15.62) ; C384.1 79.49,24.77 v2(79.5,24.78) ; C370.1 v2(96.48,42.51) ; C359.1 C381.1 v2(51.6,42.04) ; C339.2 65.28,15.11 v2(65.02,14.86) ; C376.1 v2(37.08,20.99) ; v2(72.77,46.7) C366.1 ; D18.1 v2(95.5,49.91) ; C404.1 v2(24.38,34.54) ; R371.1 79.48,37.85 v2(79.5,37.87) ; U30.1 83.19,39.11 v2(82.8,39.5) ; C396.1 v2(51.31,69.81) ; v2(50.67,23.88) C373.1 51.59,23.86 R409.2 ; C355.1 v2(54.61,19.09) ; C397.1 v2(67.6,50.71) ; C324.2 v2(23.24,34.54) ; v2(60.2,18.75) 60.62,18.75 C379.1 ; C392.1 v2(75.56,46.06) ; C325.2 v2(13.73,59.45) ; C328.2 v2(26.16,7.12) ; C378.1 v2(57.28,47.12) ; C340.1 v2(30.77,82.84) ; C375.1 v2(78.49,15.24) ; C371.1 v2(79.5,27.56) ; C323.2 v2(25.54,35.8) ; C341.1 v2(81.53,46.35)
  BOTTOM w0.152: v2(67.6,50.71) 68.77,51.88 68.77,55.44 69.42,56.08 78.6,56.08 v2(78.9,56.39)
V1.8_SENSE: length 1.9
  TOP w0.254: R411.2 56.77,20.17 U1.38
VDD3.3_AFE: length 29.1
  TOP w0.254: C384.2 77.49,24.89 U1.75 73.91,24.89 ; 73.91,24.89 73.91,24.89 71.78,22.75 U1.68 71.78,20.81 72.01,20.57 C382.2 ; 73.91,24.89 73.91,30.73 74.57,31.39 U1.88 76.99,31.39 C383.2
  TOP w0.508: C382.2 72.4,20.05 72.9,19.56 75.44,19.56 76.18,18.81 CAP16.1 FB17.2
VDD_1.8V: length 87.4
  TOP w0.254: R411.1 56.05,18.49 48.34,18.49 Q307.2
  TOP w0.508: FB13.2 31.92,79.26 C391.2 30.48,77.47 28.45,75.44 28.45,58.04 33.53,52.96 33.53,35.81 42.55,26.8 v2(42.55,25.78)
  TOP w0.533: 45.36,18.41 Q307.2 ; Q307.2 48.27,17.01 ; Q307.2 48.27,19.82 ; CAP19.1 42.66,18.36 ; CAP19.1 43.62,17.4 ; CAP19.1 42.66,16.43
  BOTTOM w0.508: CAP19.1 42.55,17.51 v2(42.55,25.78)
VDD_5V: length 50.3
  TOP w0.254: C369.2 77.58,30.89 U1.87 ; U1.80 77.44,27.39 C371.2
  TOP w0.508: v2(97.28,49.91) D18.2 96.72,48.21 96.72,43.81 97.36,43.18 FB20.2 97.36,32.84 95.9,31.38 87.5,31.38 CAP13.1 86.23,30.11 v2(77.61,30.11) C369.2 ; D19.2 101.22,49.4 100.71,49.91 v2(99.44,49.91) ; C371.2 v2(77.61,28.4)
  BOTTOM w0.508: v2(77.61,28.4) v2(77.61,30.11) ; v2(99.44,49.91) v2(97.28,49.91)
VIN: length 137.6
  TOP w0.254: R424.1 74.17,12.86 74.17,8.01 72.7,6.54 12.51,6.54 10.54,8.51 10.54,21.21
  TOP w0.533: 12.63,24.77 R342.2 13.21,25.48 ; 13.21,55.55 R329.2 ; R329.2 13.21,56.97 ; R329.2 12.63,56.26 ; CAP4.1 9.48,34.57 ; CAP4.1 8.32,33.4 ; CAP4.1 9.48,32.23 ; CAP4.1 10.65,33.4 ; C326.1 10.78,39.45 ; C326.1 10.07,38.86 ; C326.1 10.78,38.28 ; 13.21,27.36 R340.2 ; R340.2 13.21,28.78 ; R340.2 12.63,28.07 ; 13.21,53.9 R330.2 ; R330.2 12.63,54.61 ; R330.2 13.21,55.32 ; 10.07,49.78 C321.1 ; C321.1 10.78,50.37 ; C321.1 10.78,49.2 ; 16.94,58.05 U11.6 15.78,57.53 ; 14.02,31.48 C320.1 ; C320.1 15.19,31.48 ; C320.1 14.61,30.78 ; 16.94,31.76 U12.6 15.78,31.24 ; D23.2 6.45,62.74 ; D23.2 5.08,61.37 ; D23.2 5.08,64.11 ; 12.63,52.96 R331.2 ; R331.2 13.21,52.25 ; R331.2 13.21,53.67 ; 7.76,62.74 R436.2 ; R436.2 8.76,63.7 ; R436.2 8.76,61.77 ; 13.21,25.7 R341.2 ; R341.2 12.63,26.42 ; R341.2 13.21,27.13 ; CAP1.1 9.48,45.49 ; CAP1.1 9.48,43.15 ; CAP1.1 8.32,44.32 ; CAP1.1 10.65,44.32 ; 12.63,29.72 R339.2 ; R339.2 13.21,29.01 ; R339.2 13.21,30.43 ; 9.48,21.18 CAP5.1 ; CAP5.1 9.48,23.52 ; CAP5.1 10.65,22.35 ; CAP5.1 8.32,22.35 ; C325.1 15.19,57.9 ; C325.1 14.02,57.9 ; C325.1 14.61,57.19 ; CAP2.1 9.48,56.41 ; CAP2.1 9.48,54.08 ; CAP2.1 8.32,55.24 ; CAP2.1 10.65,55.24
C1M: length 1.8
  TOP w0.152: C334.2 77.59,25.89 U1.77
C1P: length 3
  TOP w0.152: C334.1 78.05,25.39 U1.76
C2M: length 3.1
  TOP w0.152: U1.62 68.77,20.76 68.95,20.59 68.95,19.58 C335.2
C2P: length 1.9
  TOP w0.152: U1.63 69.27,20.22 C335.1
C3M: length 3.2
  TOP w0.152: U1.64 69.78,20.76 70.09,20.45 70.09,19.58 C336.2
C3P: length 2
  TOP w0.152: U1.65 70.28,20.78 70.61,20.45 C336.1
CONTROL_1.8V: length 13.3
  TOP w0.254: Q307.1 50.98,16.82 51.82,17.65 v2(53.47,17.65) 53.9,18.08 56.44,18.08 57.27,18.92 U1.39 ; v2(53.47,19.18) 53.47,19.9 C389.1
  BOTTOM w0.254: v2(53.47,17.65) v2(53.47,19.18)
CREFM: length 1.9
  TOP w0.152: C337.2 77.35,23.89 U1.73
CREFP: length 3.1
  TOP w0.152: C337.1 78.01,24.19 76.9,24.19 76.71,24.39 U1.74
DATA: length 34
  TOP w0.152: U1.15 56.54,34.39 57.23,33.71 57.23,23.65 v2(56.82,23.24)
  BOTTOM w0.152: 58.29,3.94 56.59,5.64 56.59,23.01 v2(56.82,23.24)
DG_SENSE: length 6
  TOP w0.152: U1.66 70.78,20.73 71.13,20.37 71.13,17.9 R424.2 70.6,17.36 R423.1
EJTAG_TCK: length 5.9
  TOP w0.152: U1.53 64.27,20.71 64,20.43 64,18.88 64.85,18.03 65.16,18.03 65.82,17.38 R379.2
